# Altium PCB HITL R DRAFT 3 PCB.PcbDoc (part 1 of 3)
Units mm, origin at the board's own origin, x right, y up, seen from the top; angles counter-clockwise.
Board outline 90 x 65 mm, 6 copper layers (L1, L2, L3, L4, L5, L6), stack 1.752 mm thick; 198 components, 194 nets, 830 pads, 458 vias.
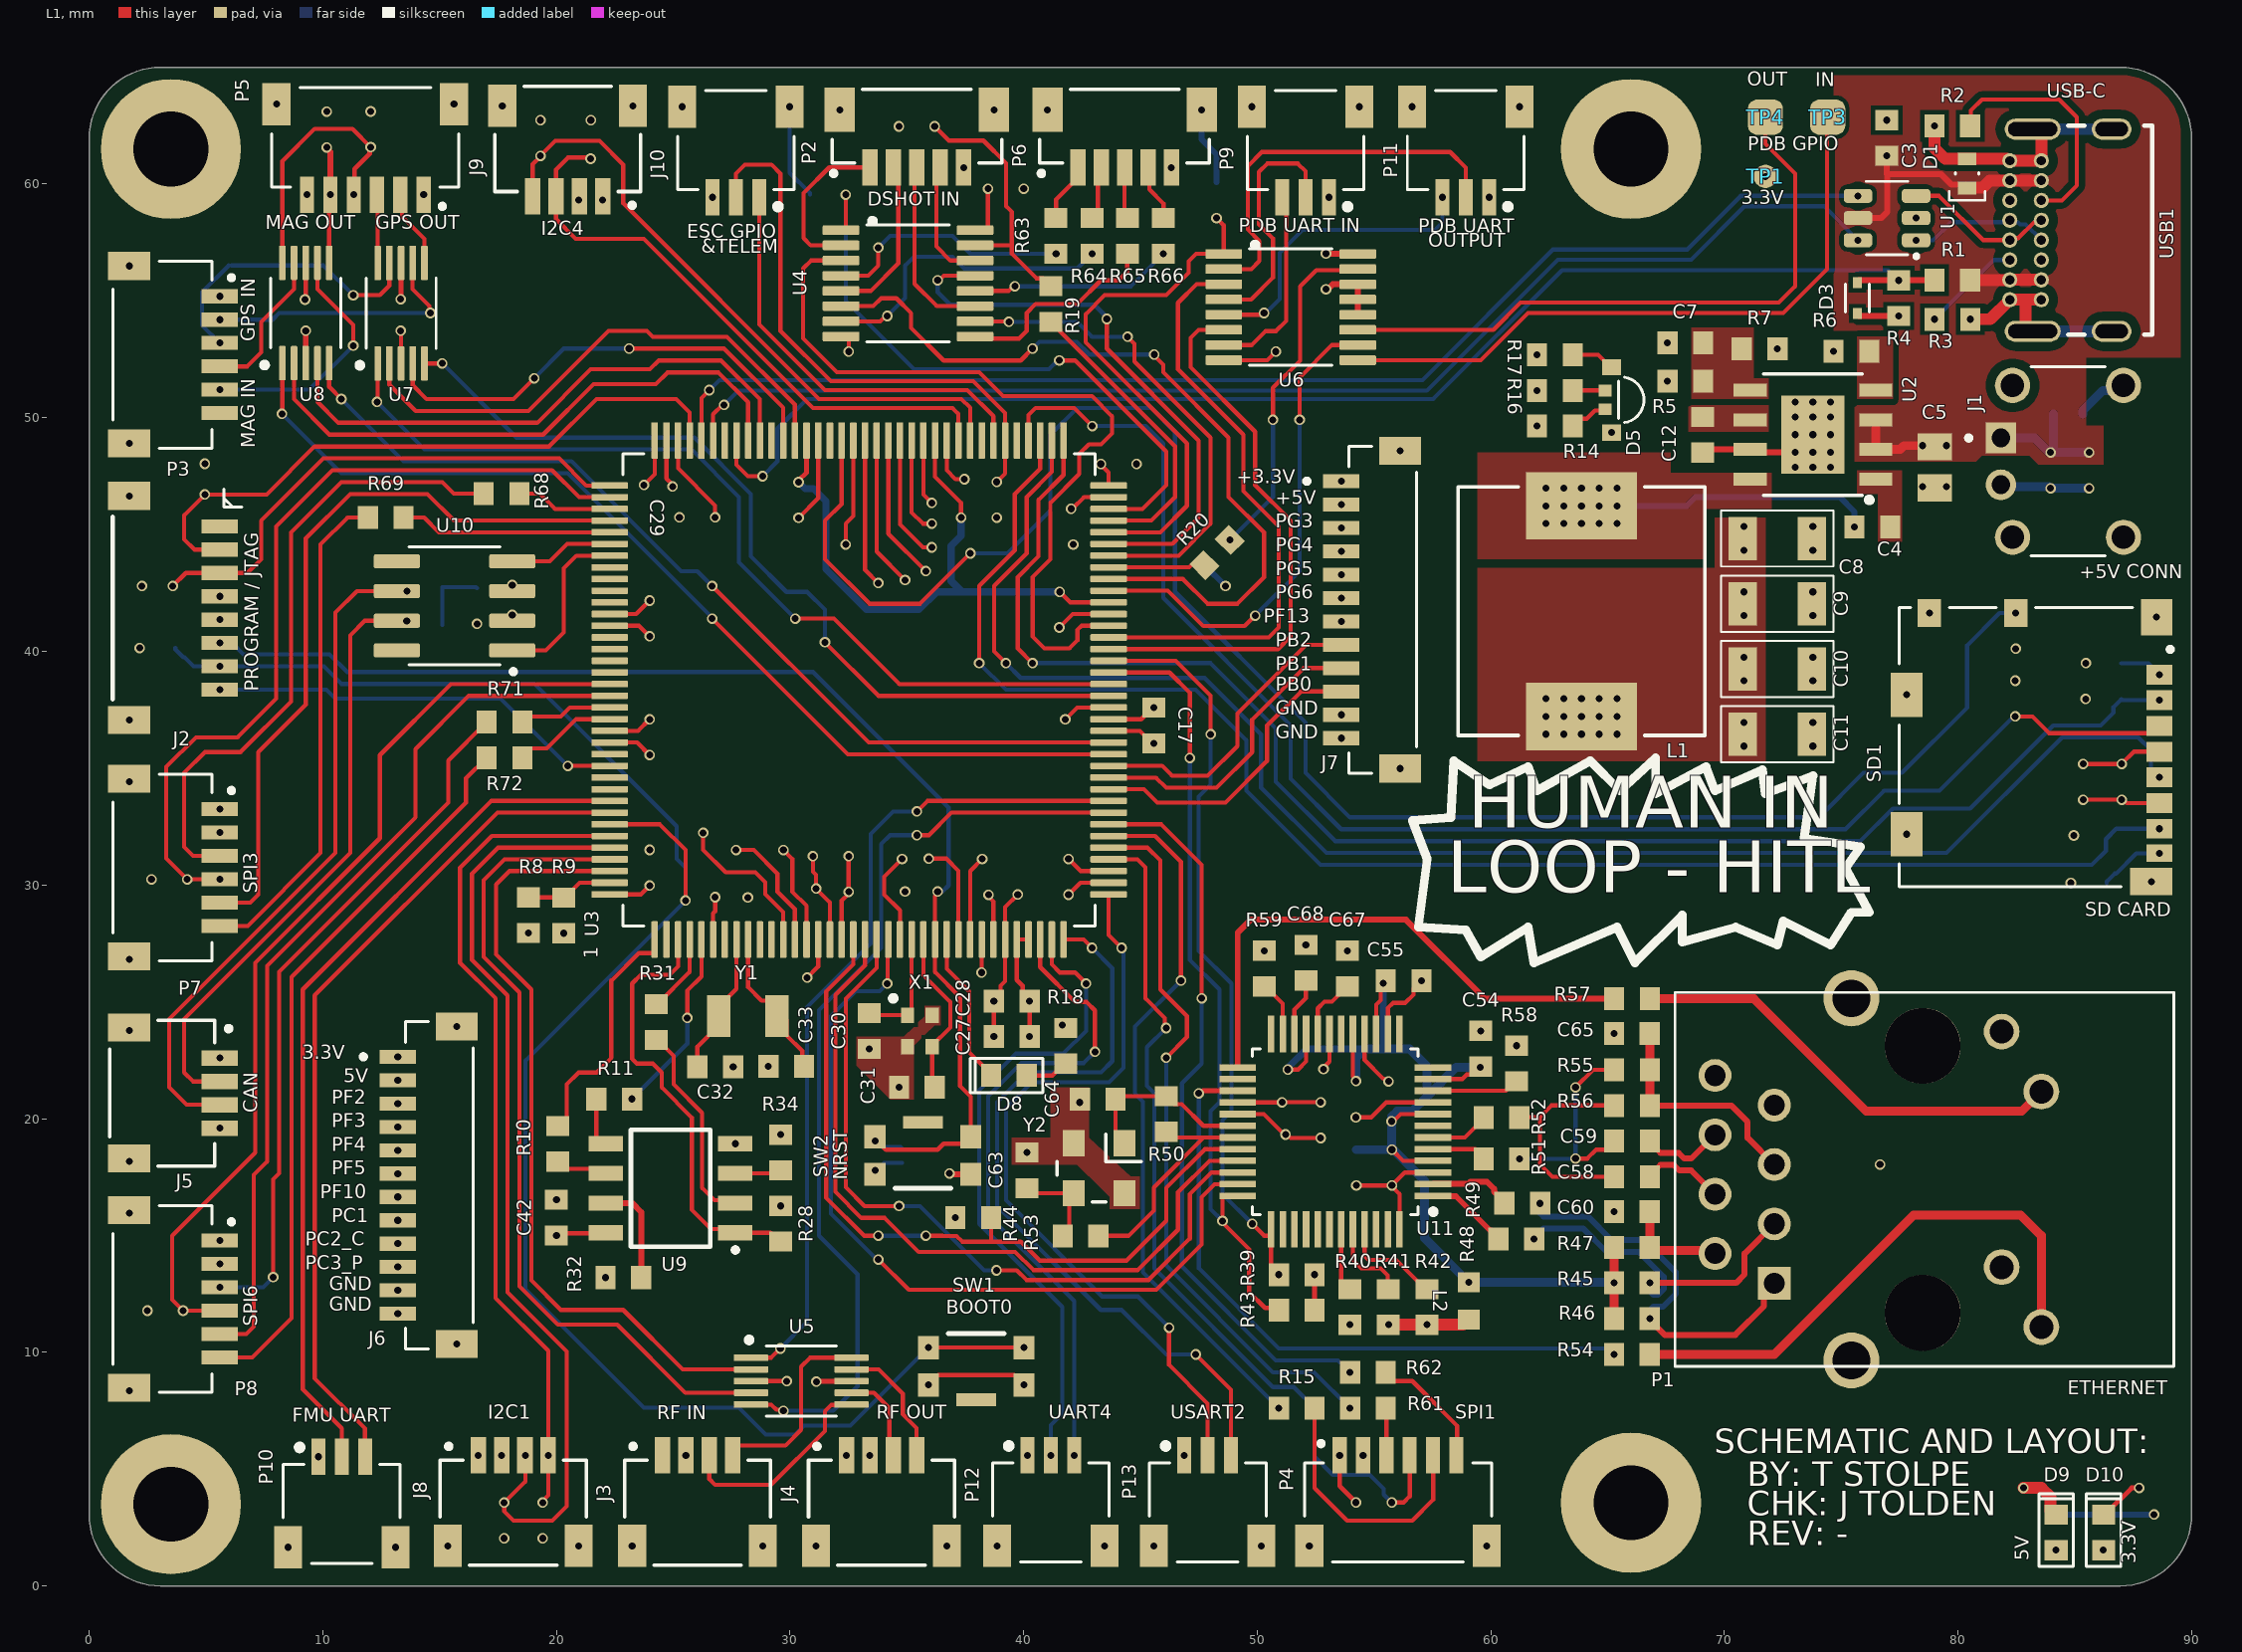
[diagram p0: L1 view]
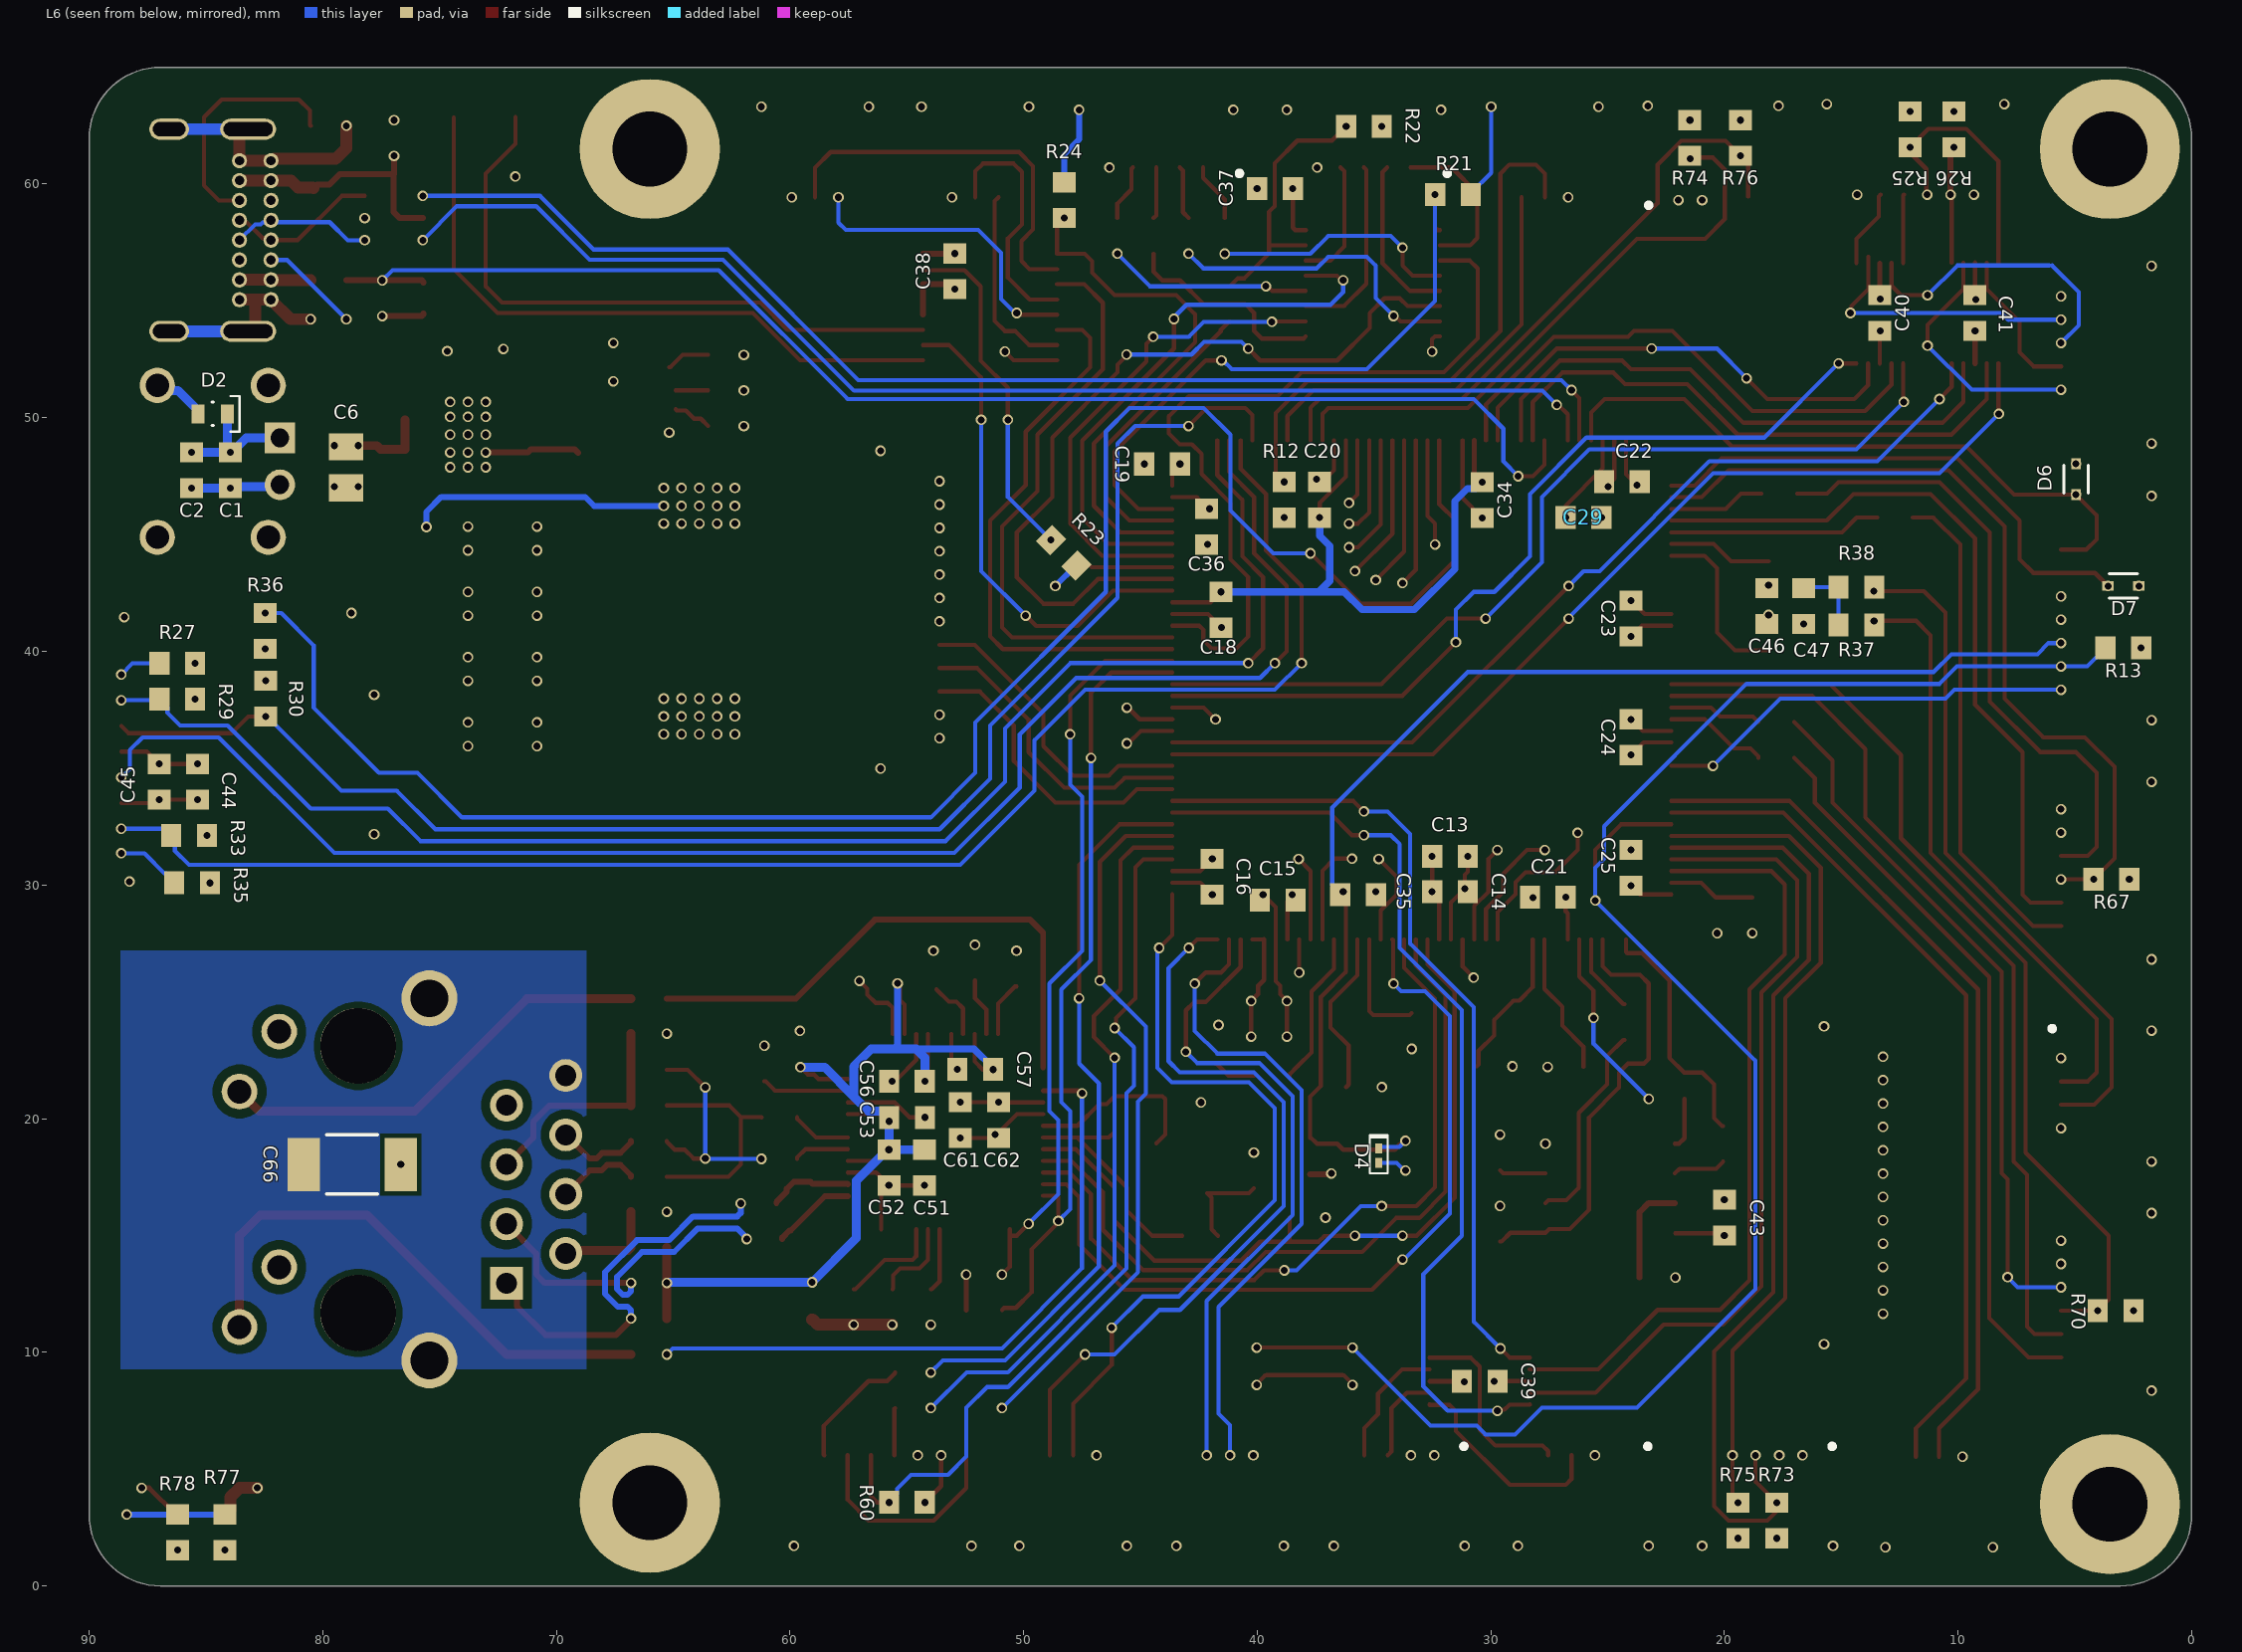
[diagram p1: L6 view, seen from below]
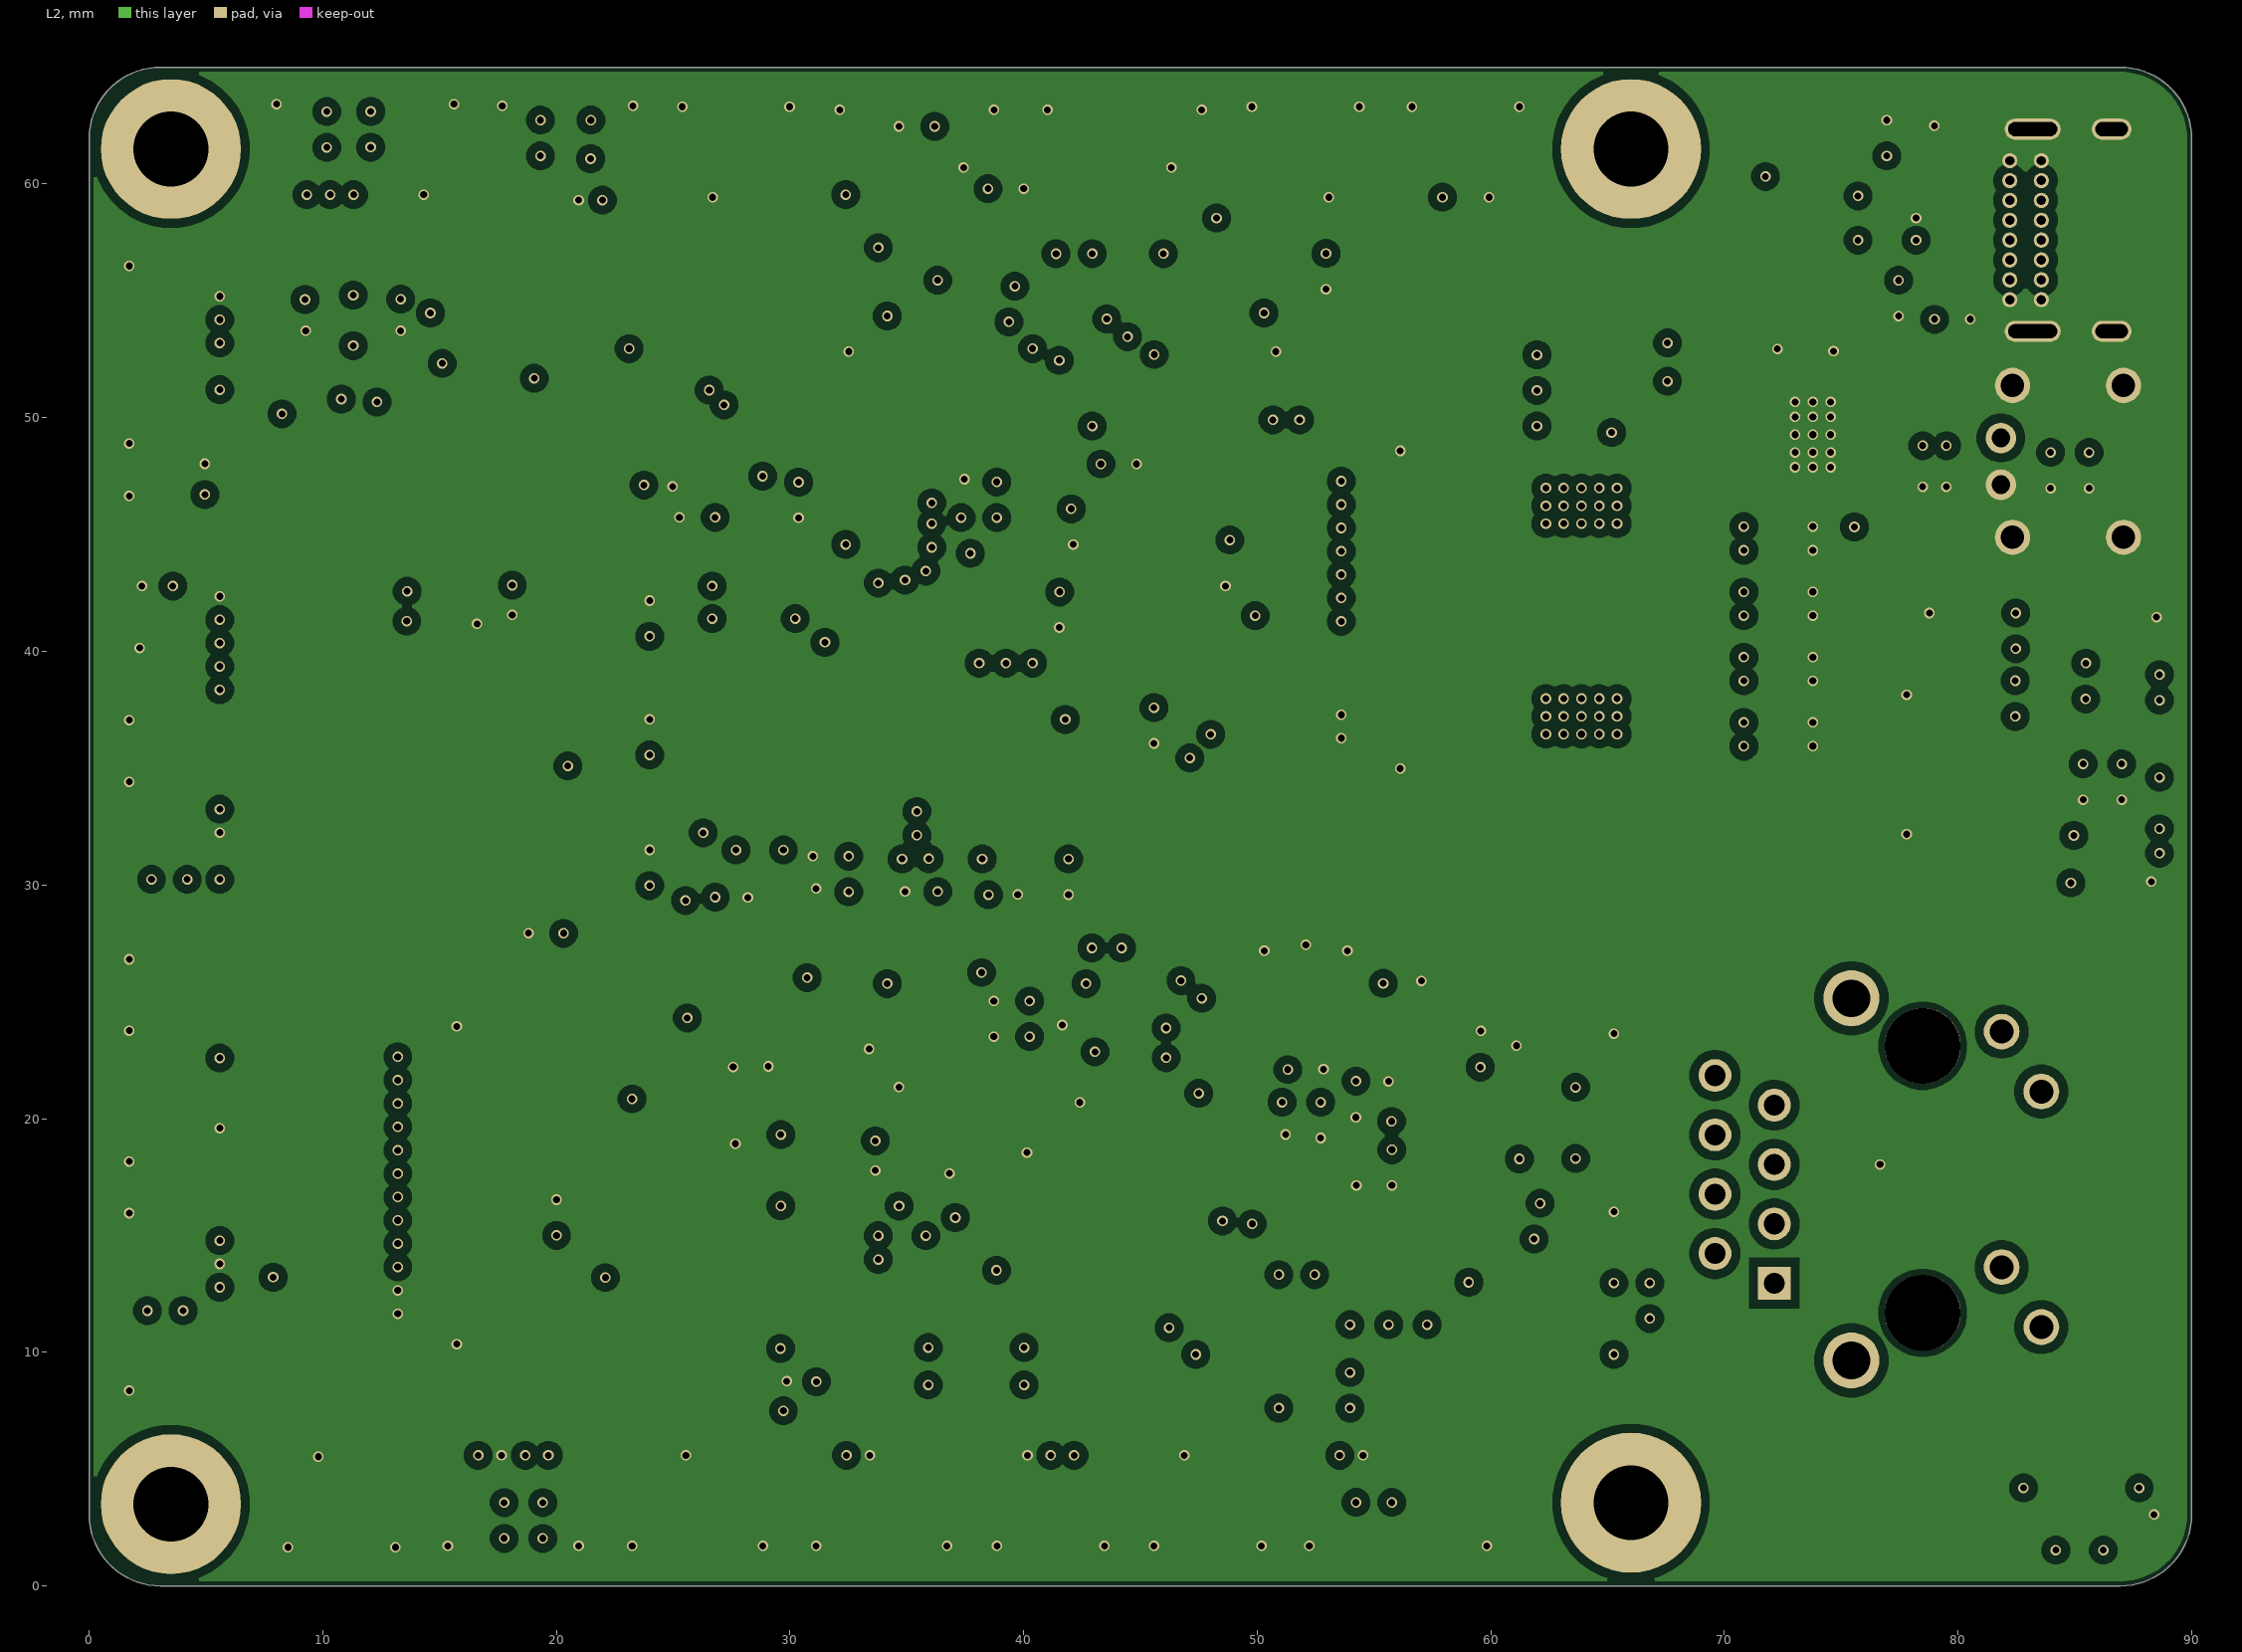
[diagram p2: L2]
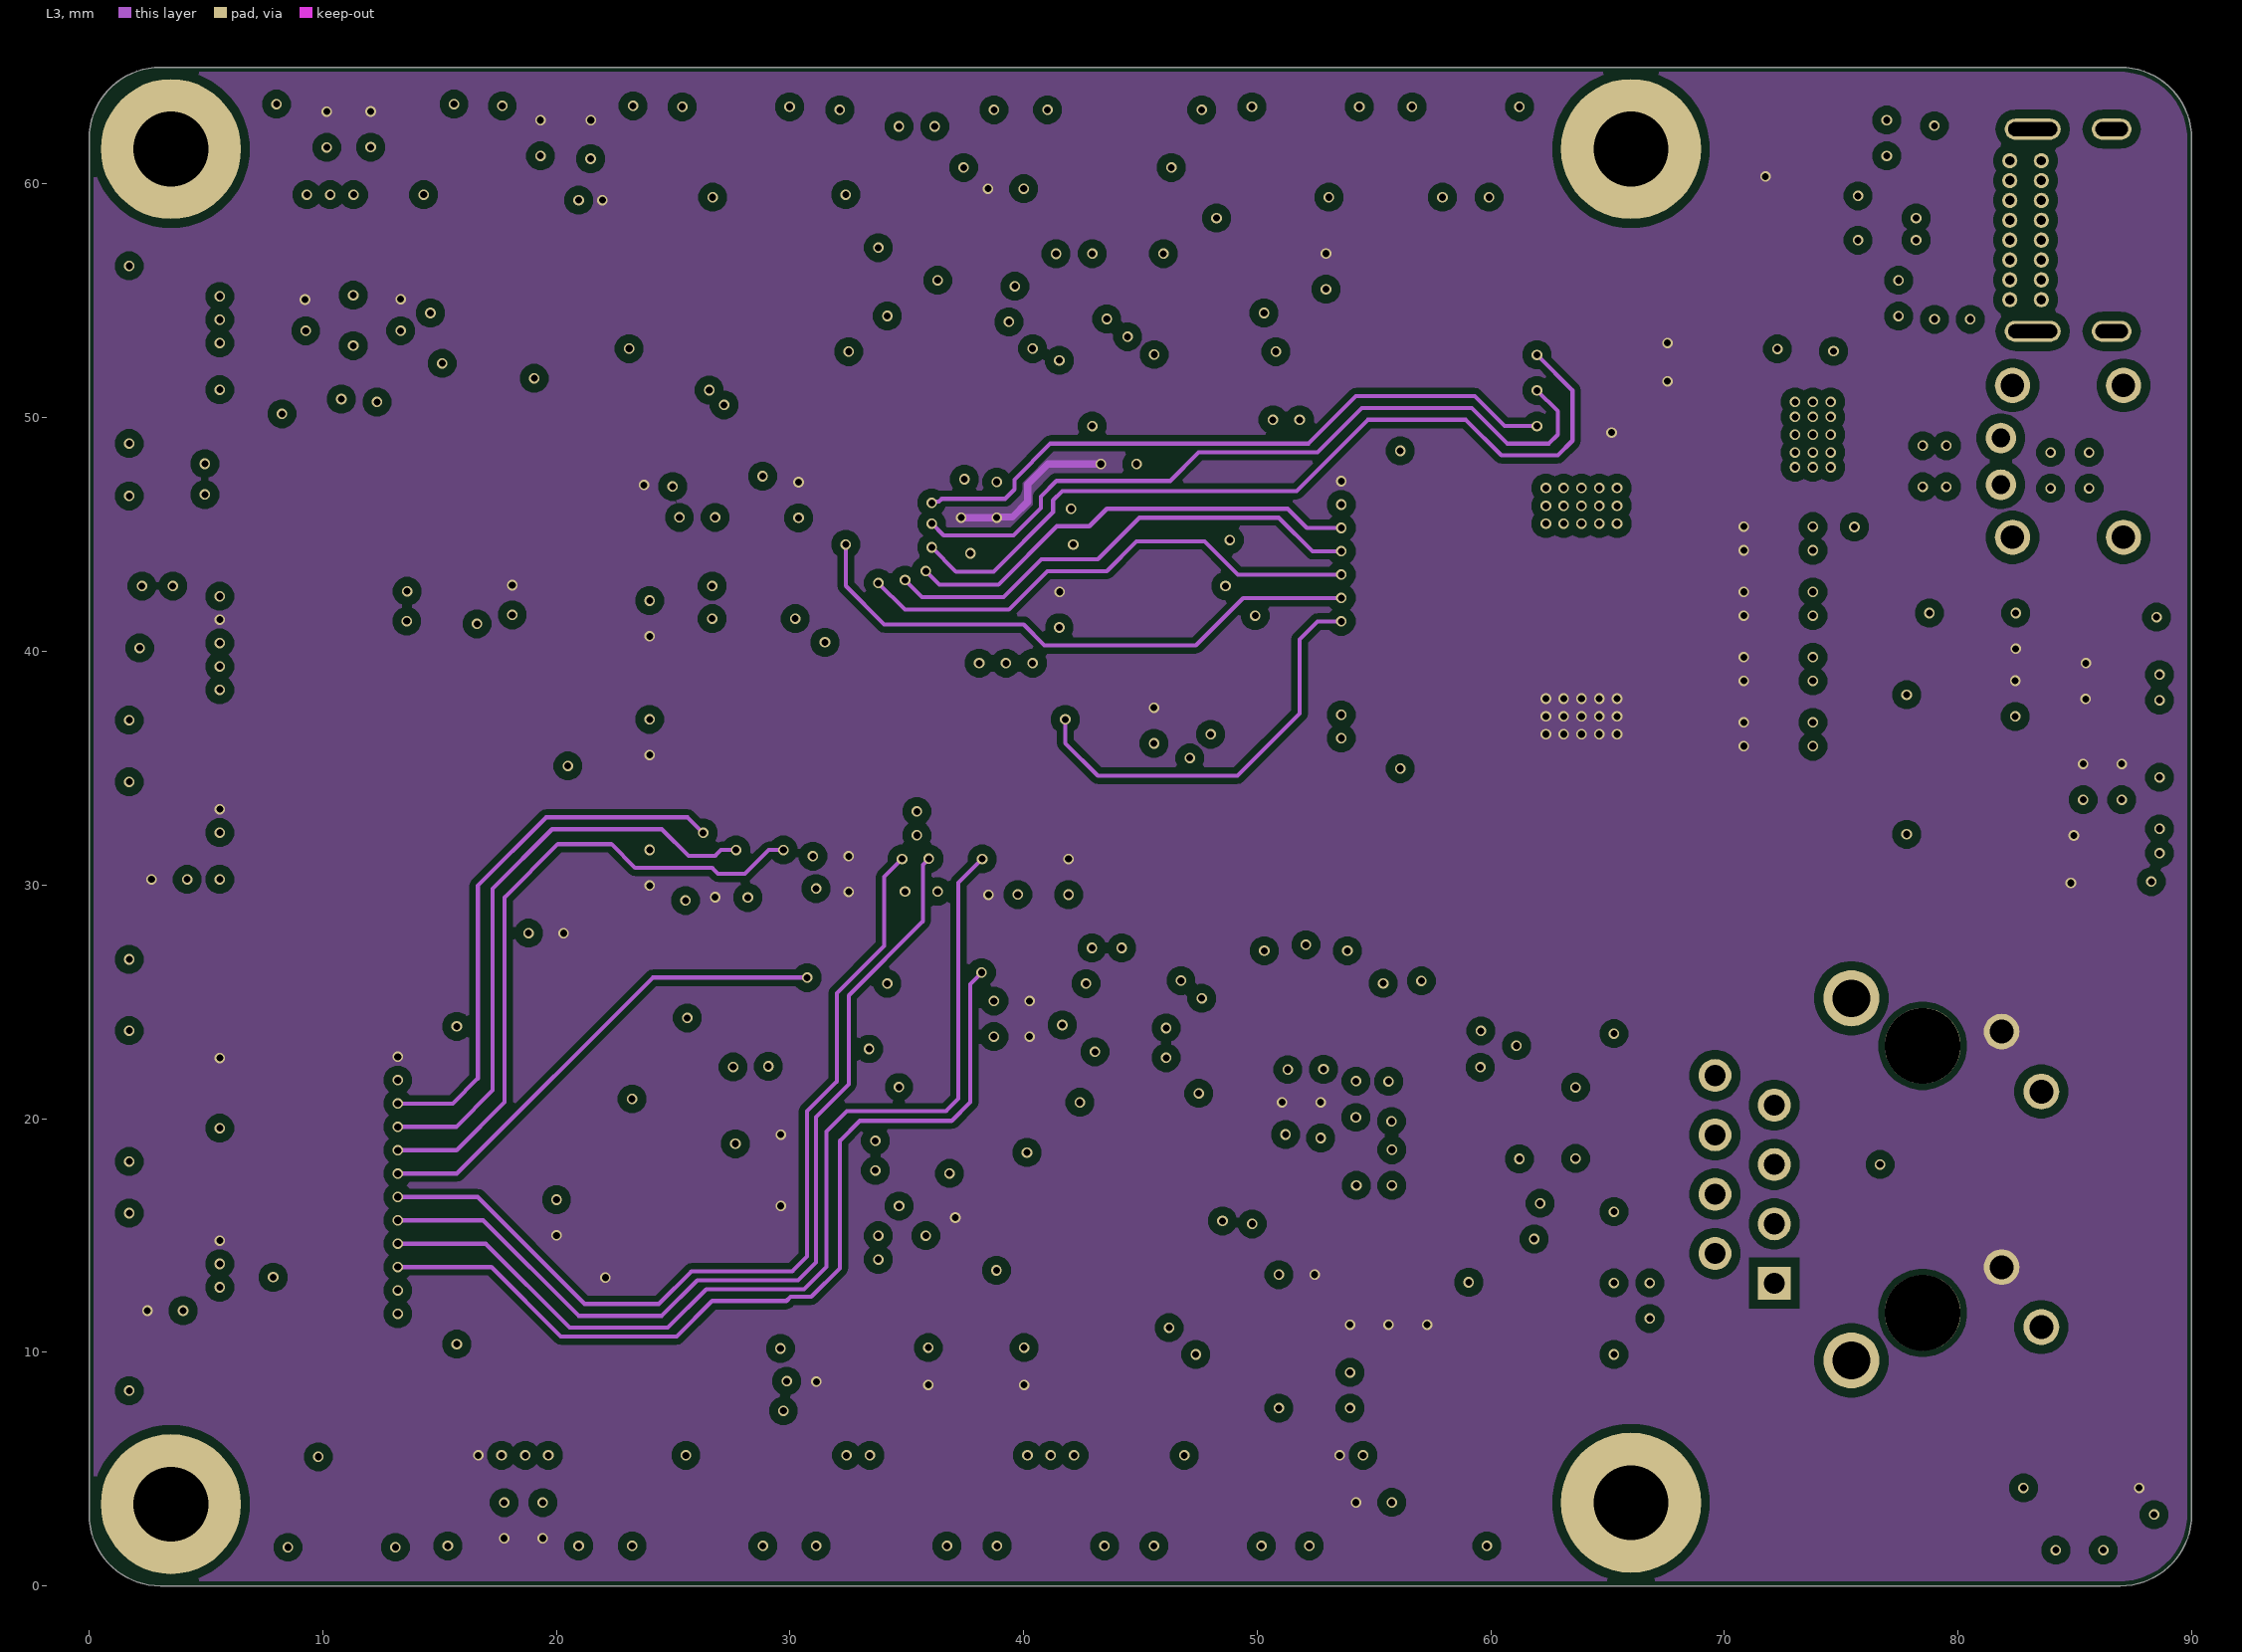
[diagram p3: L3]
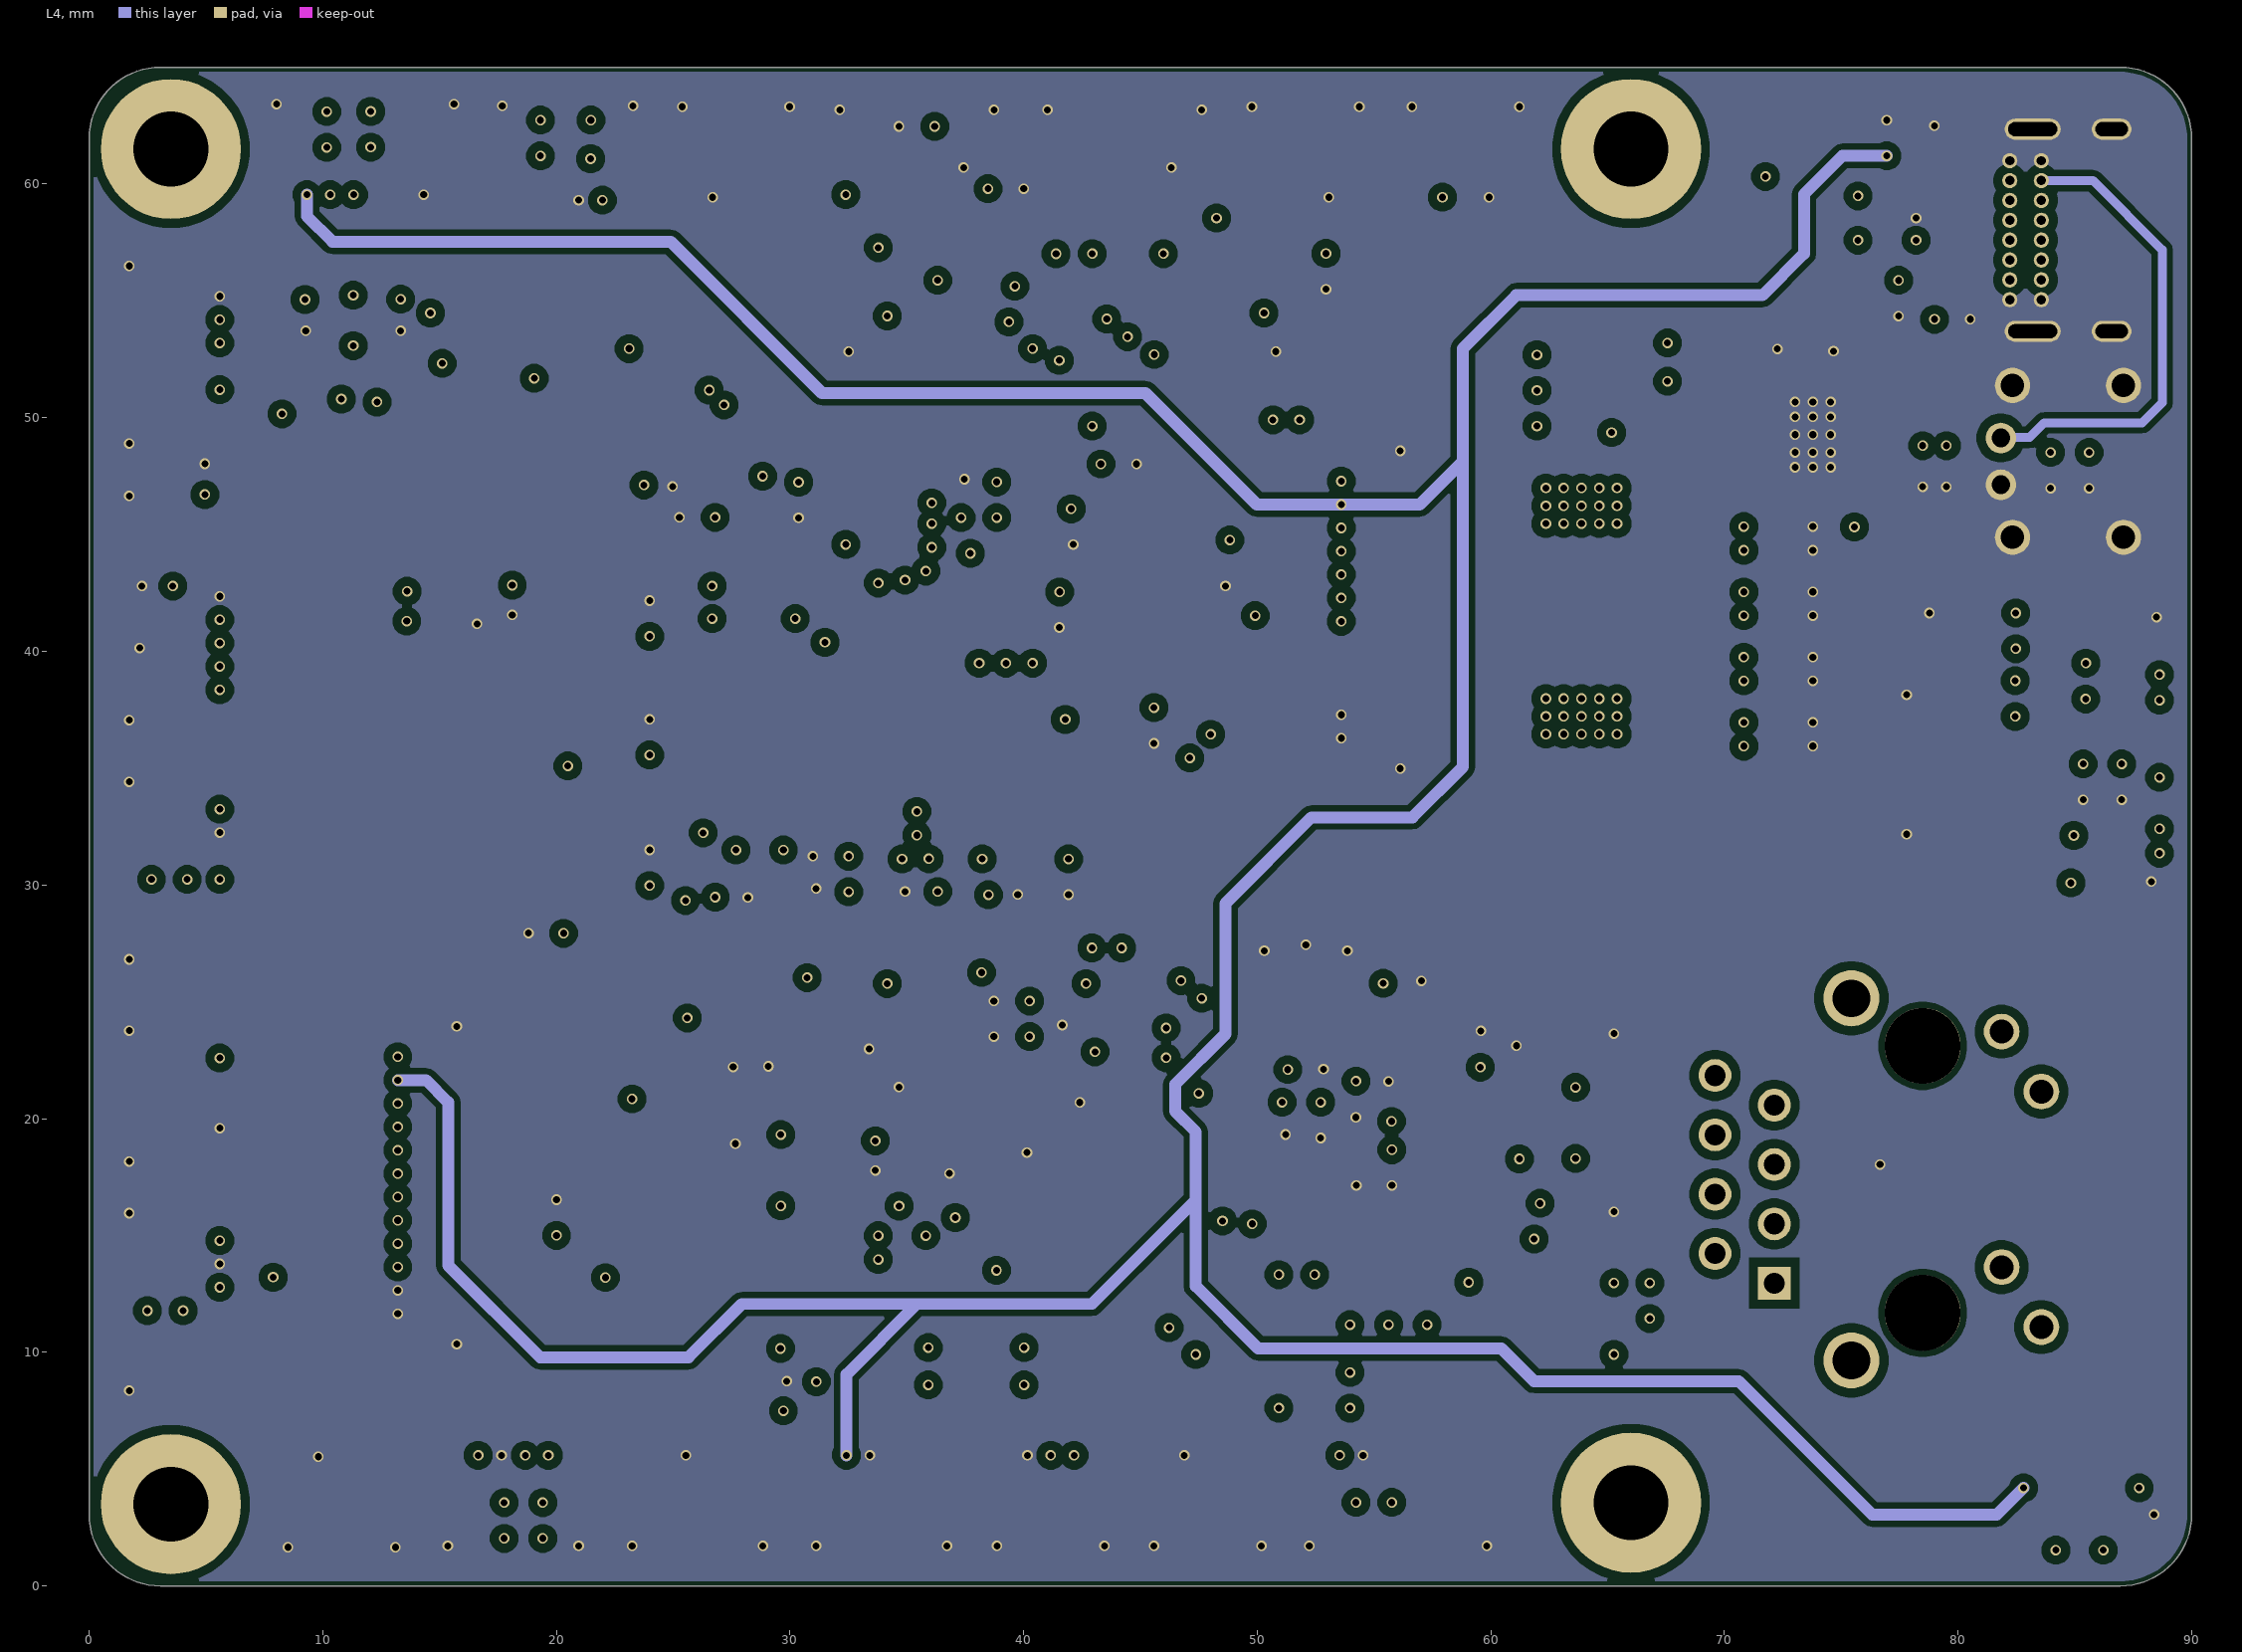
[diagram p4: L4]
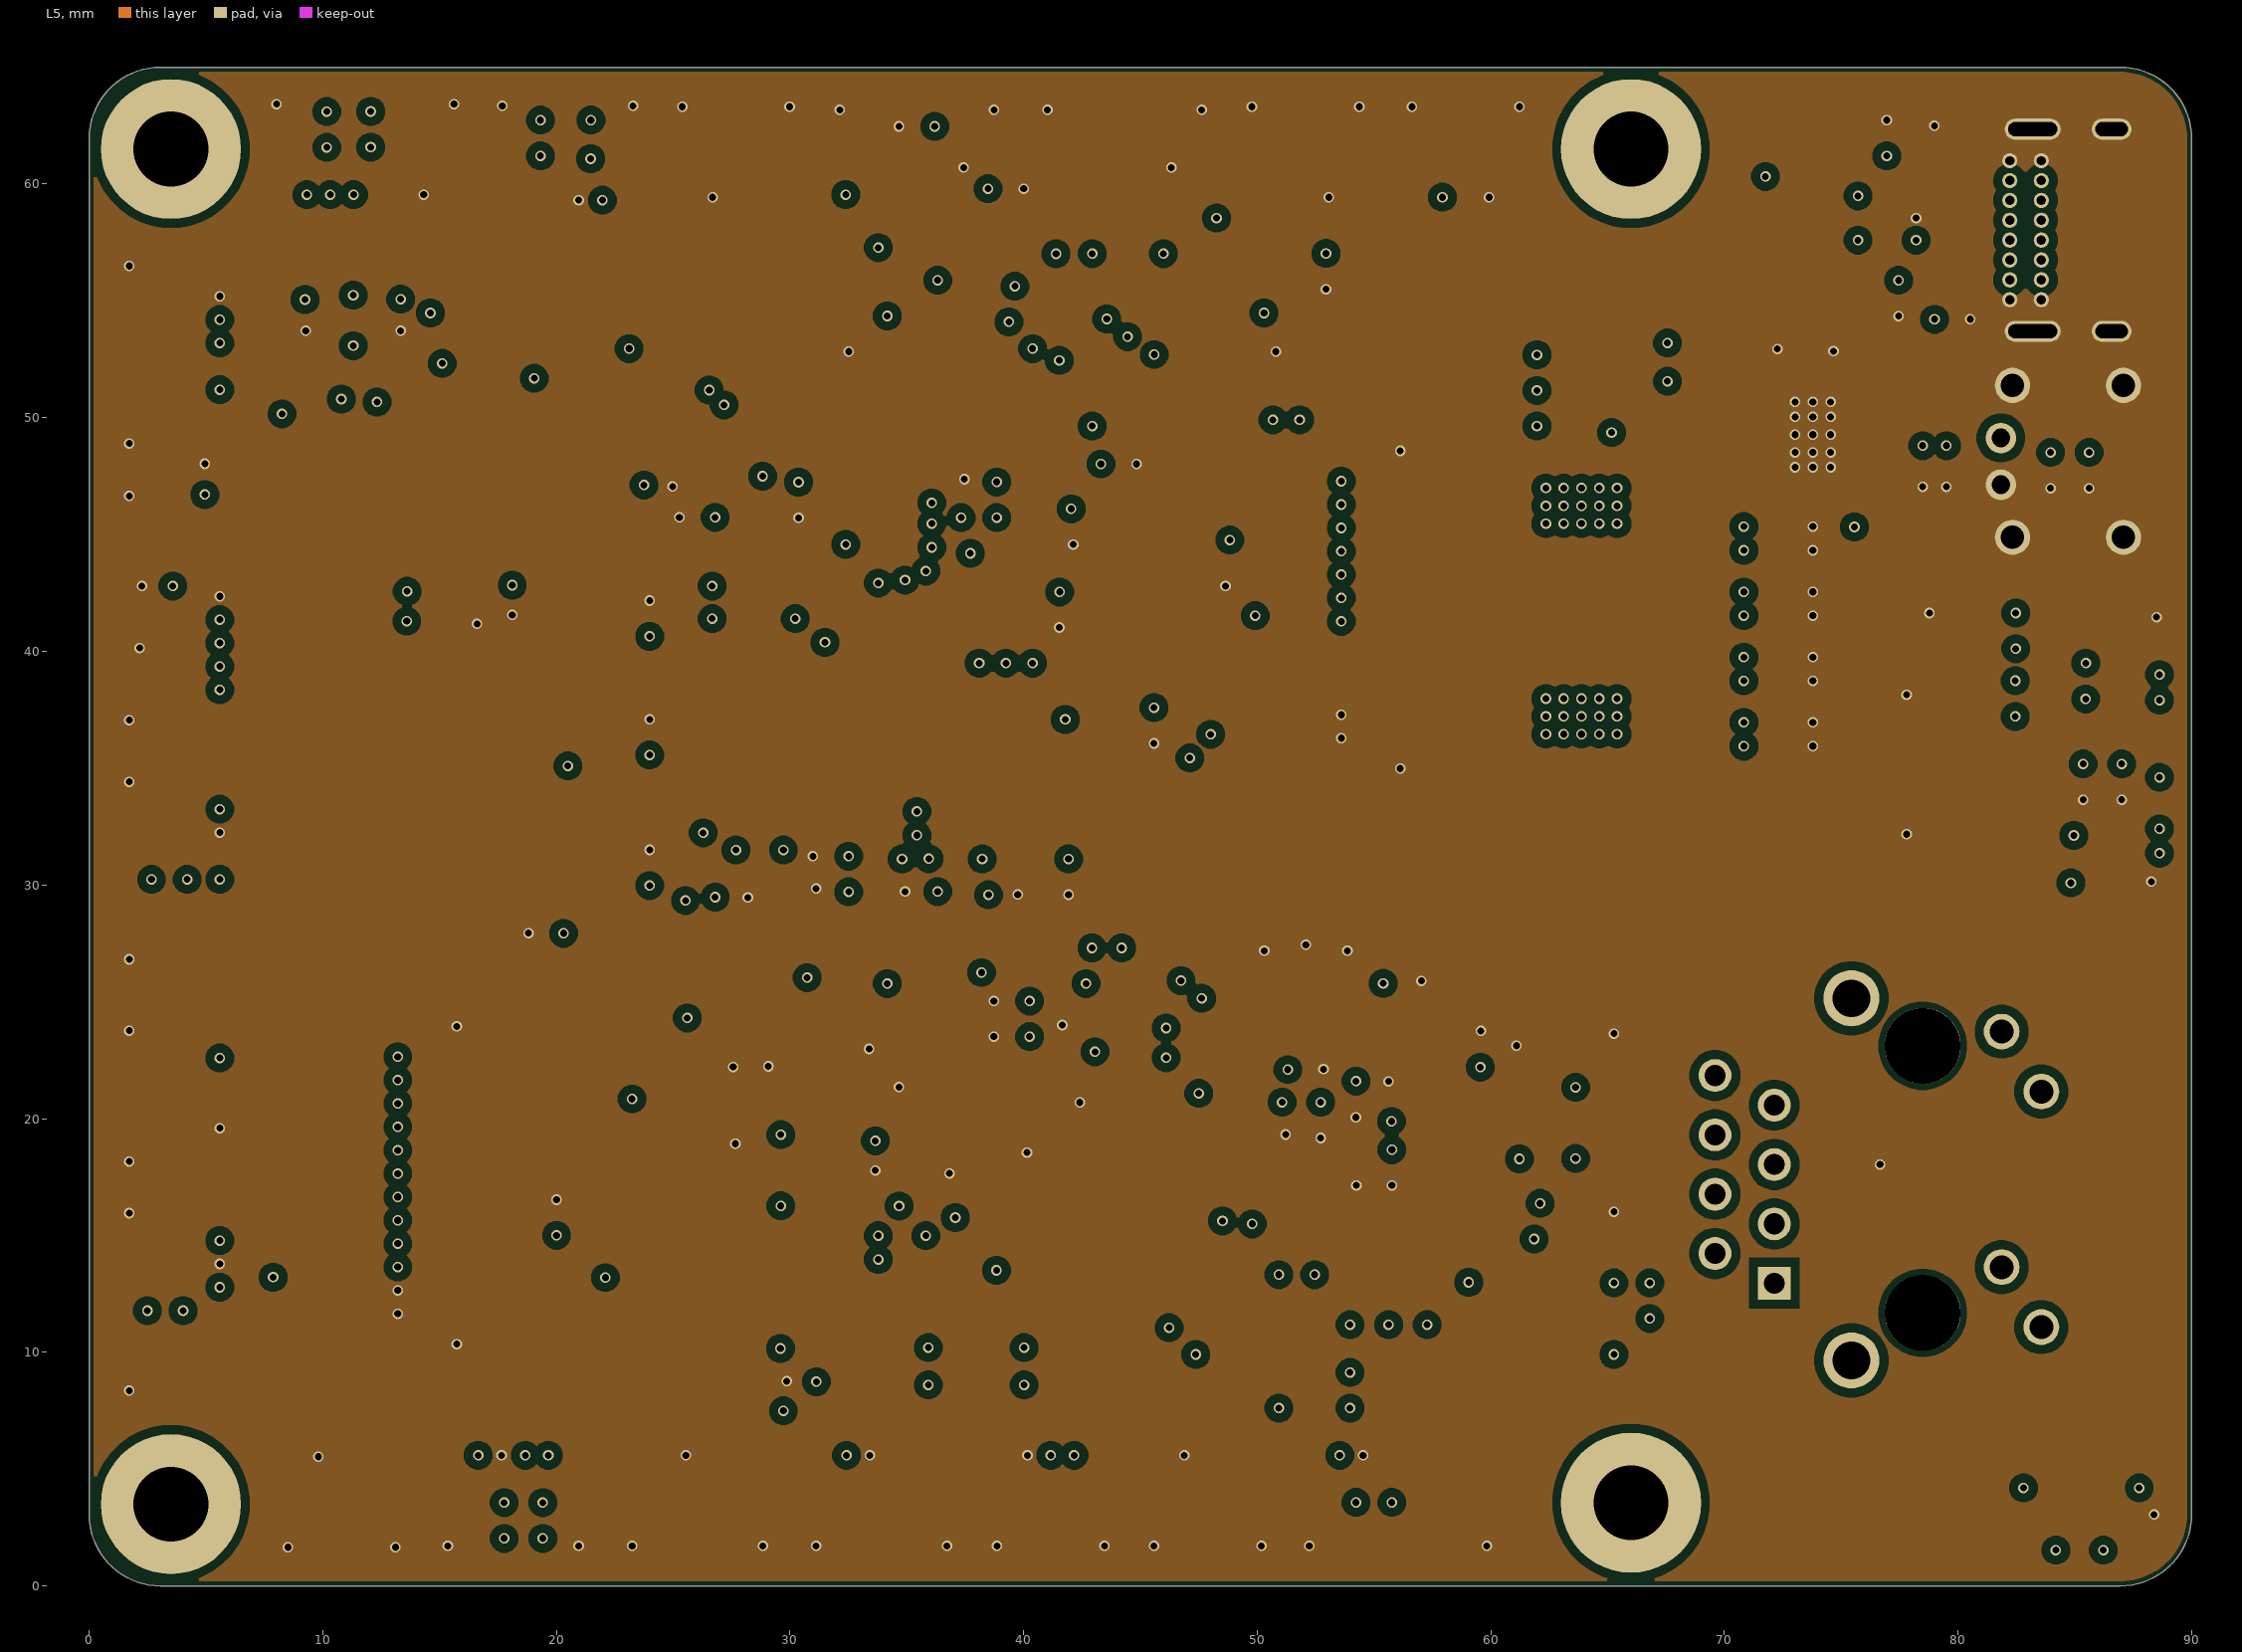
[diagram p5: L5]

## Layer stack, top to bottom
Top Solder: solder mask 0.0102, Solder Resist, Dk 3.5
L1: signal copper 0.035
Dielectric 1: prepreg 0.0711, PP-006, Dk 4.1
L2: signal copper 0.035
PREPREG1: prepreg 0.2, PP-006, Dk 4.1
L3: signal copper 0.035
CORE: core 1, Core-042, Dk 4.6
L4: signal copper 0.035
PREPREG2: prepreg 0.2, PP-006, Dk 4.1
L5: signal copper 0.035
Dielectric 2: prepreg 0.0711, PP-006, Dk 4.1
L6: signal copper 0.035
Bottom Solder: solder mask 0.0102, Solder Resist, Dk 3.5

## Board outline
0,3.048 0,61.952 cw(c3.048,61.952) 3.048,65 86.952,65 cw(c86.952,61.952) 90,61.952 90,3.048 cw(c86.952,3.048) 86.952,0 3.048,0 cw(c3.048,3.048)

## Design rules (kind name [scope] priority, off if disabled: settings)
BoardOutlineClearance [All] p1: gap=0.2 ignorepadtopadclearanceinfootprint=FALSE
Clearance [All] p1: gap=0.254 ignorepadtopadclearanceinfootprint=TRUE except(0.152: Arc-Arc Arc-Track Arc-THPad Track-Track Track-THPad SMDPad-SMDPad SMDPad-THPad SMDPad-Via SMDPad-Text THPad-THPad THPad-Via THPad-Text Via-Via Via-Text Fill-Text Poly-Text Region-Text Text-Text; 0.178: SMDPad-Fill SMDPad-Poly SMDPad-Region; 0.203: Arc-SMDPad Track-SMDPad; 0.381: THPad-Fill THPad-Poly THPad-Region Via-Fill Via-Poly Via-Region; 0.457: SMDPad-Hole THPad-Hole)
ComponentClearance [All] p1: gap=0.102 collisioncheckmode=3 verticalgap=0.102 showdistances=TRUE
DiffPairsRouting [All] p1: maxlimit=0.508 minlimit=0.254 mostfreqgap=0.254 toplayer_minwidth=0.178 toplayer_maxwidth=0.635 toplayer_prefwidth=0.178 midlayer1_minwidth=0.178 midlayer1_maxwidth=0.635 midlayer1_prefwidth=0.178 midlayer2_minwidth=0.178 midlayer2_maxwidth=0.635 midlayer2_prefwidth=0.178 midlayer3_minwidth=0.178 midlayer3_maxwidth=0.635 midlayer3_prefwidth=0.178 midlayer4_minwidth=0.178 midlayer4_maxwidth=0.635 midlayer4_prefwidth=0.178 bottomlayer_minwidth=0.178 bottomlayer_maxwidth=0.635 bottomlayer_prefwidth=0.178 maxuncoupledlength=12.7
Height [All] p1: minheight=0 maxheight=1816.048 prefheight=12.7
HoleSize [All] p1: absolutevalues=TRUE maxlimit=6.3 minlimit=0.3 maxpercent=80.000 minpercent=20.000
HoleToHoleClearance [All] p1: gap=0.203 allowstackedmicrovias=FALSE
MinimumAnnularRing [All] p1: minimumring=0
MinimumSolderMaskSliver [All] p1: minsoldermaskwidth=0
PlaneClearance [All] p1: clearance=0.102
PlaneConnect PlaneConnectPowerPads [InPadClass('PowerPads')] p1: planeconnectstyle=Direct reliefexpansion=0.508 reliefentries=4 reliefconductorwidth=0.254 reliefairgap=0.254
PlaneConnect [All] p2: planeconnectstyle=Direct reliefexpansion=0.3 reliefentries=4 reliefconductorwidth=0.102 reliefairgap=0.102
PolygonConnect PolygonConnectPowerPads [All vs (InPadClass('PowerPads'))] p1: connectstyle=Direct reliefconductorwidth=0.254 reliefentries=4 polygonreliefangle="90 Angle" airgapwidth=0.254
PolygonConnect [All] p2: connectstyle=Direct reliefconductorwidth=0.102 reliefentries=4 polygonreliefangle="90 Angle" airgapwidth=0.102
RoutingVias [All] p1: holewidth=0.3 width=0.45 viastyle="Through Hole" minholewidth=0.299 minwidth=0.449 maxholewidth=0.301 maxwidth=0.452
SilkToSilkClearance [All] p1: silktosilkclearance=0
SilkToSolderMaskClearance [IsPad] p1: minsilkscreentomaskgap=0 clearancetoexposedcopper=TRUE
SolderMaskExpansion [All] p1: expansion=0.075 istentingtop=FALSE
SupplyNets "Schematic Supply Nets_11" [InNet('CGND')] p1: voltage=0.000
SupplyNets "Schematic Supply Nets_8" [InNet('+3.3V')] p2: voltage=0.000
SupplyNets "Schematic Supply Nets_5" [InNet('+5V')] p3: voltage=0.000
SupplyNets "Schematic Supply Nets_2" [InNet('+3V3A')] p4: voltage=0.000
SupplyNets "Schematic Supply Nets_1" [InNet('GND')] p5: voltage=0.000
Width [All] p1: maxlimit=1816.048 minlimit=0.102 preferedwidth=0.178
20 further rules are at their usual default settings.

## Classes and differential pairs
differential pair class USB_LINES: D
component class "HITL (PWR) SH2": C1 C2 C3 C4 C5 C6 C7 C8 C9 C10 C11 C12 D1 D2 D3 D9 D10 J1 L1 R1 R2 R3 R4 R5 R6 R7 R77 R78 TP1 U1 U2 USB1
component class "HITL (MUX) SH4": C37 C38 C39 C40 C41 R19 R20 R21 R22 R23 R24 R25 R26 U4 U5 U6 U7 U8
component class "HITL (MEMORY) SH5": C42 C43 C44 C45 R27 R28 R29 R30 R31 R32 R33 R34 R35 R36 SD1 U9
component class "HITL (MCU) SH3": C13 C14 C15 C16 C17 C18 C19 C20 C21 C22 C23 C24 C25 C27 C28 C29 C30 C31 C32 C33 C34 C35 C36 D4 D5 D6 D7 D8 J2 R8 R9 R10 R11 R12 R13 R14 R15 R16 R17 R18 SW1 SW2 U3 X1 Y1
component class "HITL (INTRFACE 2) SH7": J3 J4 J5 J6 J7 J8 J9 J10 P2 P3 P4 P5 P6 P7 P8 P9 P10 P11 P12 P13 R60 R61 R62 R63 R64 R65 R66 R67 R68 R69 R70 R71 R72 R73 R74 R75 R76 TP3 TP4
component class "HITL (INTRFACE 1) SH6": C46 C47 C51 C52 C53 C54 C55 C56 C57 C58 C59 C60 C61 C62 C63 C64 C65 C66 C67 C68 L2 P1 R37 R38 R39 R40 R41 R42 R43 R44 R45 R46 R47 R48 R49 R50 R51 R52 R53 R54 R55 R56 R57 R58 R59 U10 U11 Y2
differential pair TX: +TX_P -TX_N
differential pair TX3: +TX3_P -TX3_N
differential pair RX: +RX_P -RX_N
differential pair RX3: +RX3_P -RX3_N
differential pair RX2: +RX2_P -RX2_N
differential pair DOUT: +DOUT_P -DOUT_N
differential pair D: +D_P -D_N

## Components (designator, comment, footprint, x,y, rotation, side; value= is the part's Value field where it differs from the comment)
C1 "100nF" 0603#1 83.947,47.752 r90 bottom
C2 "1uF" 0603#1 85.598,47.752 r90 bottom
C3 "100nF" 0603#1 76.962,61.976 r90 top
C4 "100nF" 0603#1 76.327,45.339 r180 top
C5 "10uF" 0805 78.994,47.879 r90 top
C6 "10uF" 0805 78.994,47.879 r90 bottom
C7 "DNI" 0603#1 68.326,53.213 r180 top
C8 "47uF" 1206 72.263,44.831 r180 top
C9 "47uF" 1206 72.263,42.037 r180 top
C10 "47uF" 1206 72.263,39.243 r180 top
C11 "47uF" 1206 72.263,36.449 r180 top
C12 "10nF" 0603#1 69.088,49.276 r90 top
C13 "4.7uF" 0603#1 31.75,31.242 r0 bottom
C14 "100nF" 0603#1 31.75,29.718 r0 bottom
C15 "100nF" 0603#1 39.116,29.337 r180 bottom
C16 "100nF" 0603#1 41.91,30.353 r90 bottom
C17 "100nF" 0603#1 45.593,36.83 r90 top
C18 "100nF" 0603#1 41.529,41.783 r90 bottom
C19 "100nF" 0603#1 44.069,48.006 r180 bottom
C20 "100nF" 0603#1 37.338,46.482 r270 bottom
C21 "100nF" 0603#1 27.559,29.464 r180 bottom
C22 "100nF" 0603#1 24.384,47.244 r180 bottom
C23 "100nF" 0603#1 24.003,41.402 r270 bottom
C24 "100nF" 0603#1 24.003,36.322 r270 bottom
C25 "100nF" 0603#1 24.003,30.734 r270 bottom
C27 "1uF" 0603#1 39.497,23.495 r0 top
C28 "100n" 0603#1 39.497,25.019 r0 top
C29 "2.2uF" 0603#2 26.035,45.72 r0 bottom
C30 "6pF" 0603#1 33.401,23.749 r90 top
C31 "6pF" 0603#1 35.433,21.336 r0 top
C32 "6pF" 0603#1 26.797,22.225 r180 top
C33 "6pF" 0603#1 29.845,22.225 r0 top
C34 "1uF" 0603#1 30.353,46.482 r90 bottom
C35 "100nF" 0603#1 35.687,29.591 r0 bottom
C36 "2.2uF" 0603#1 42.164,45.339 r90 bottom
C37 "100nF" 0603#1 39.243,59.817 r0 bottom
C38 "100nF" 0603#1 52.959,56.261 r270 bottom
C39 "100nF" 0603#1 30.48,8.763 r0 bottom
C40 "100nF" 0603#1 13.335,54.483 r90 bottom
C41 "100nF" 0603#1 9.271,54.483 r90 bottom
C42 "100nF" 0603#1 19.992,15.759 r270 top
C43 "4.7uF" 0603#1 20.018,15.759 r270 bottom
C44 "1uF" 0603#1 85.344,34.417 r90 bottom
C45 "0.1uF" 0603#1 86.995,34.417 r90 bottom
C46 "100nF" 0603#1 18.18,41.944 r90 bottom
C47 "4.7nF" 0603#1 16.587,41.944 r90 bottom
C51 "1uF" 0603#1 54.229,17.907 r90 bottom
C52 "100nF" 0603#1 55.753,17.907 r90 bottom
C53 "100nF" 0603#1 54.991,20.066 r0 bottom
C54 "100nF" 0603#1 59.563,22.987 r270 top
C55 "100nF" 0603#1 56.261,25.908 r180 top
C56 "100nF" 0603#1 54.991,21.59 r180 bottom
C57 "100nF" 0603#1 52.07,22.098 r180 bottom
C58 "6.8nF" 0603#1 66.04,17.526 r180 top
C59 "6.8nF" 0603#1 66.04,19.05 r180 top
C60 "22nF" 0603#1 66.04,16.002 r0 top
C61 "10uF" 0603#1 52.705,19.939 r90 bottom
C62 "100nF" 0603#1 51.054,19.939 r90 bottom
C63 "33pF" 0603#1 40.132,17.78 r270 top
C64 "33pF" 0603#1 43.18,20.828 r0 top
C65 "10nF" 0603#1 66.04,23.622 r0 top
C66 "1808GC102KAT2A" CAP_1808_AVX 78.74,18.034 r0 bottom
C67 "4.7uF" 0603#1 53.848,26.416 r270 top
C68 "10nF" 0603#1 52.07,26.67 r270 top
D1 "ESDA7P120-1U1M" TVS_ESDA7P120-1U1M 80.391,60.452 r90 top
D2 "ESDA7P120-1U1M" TVS_ESDA7P120-1U1M 84.709,50.165 r0 bottom
D3 "LESD5D5.0CT1G" TVS_LESD5D5.0CT1G 75.692,55.118 r270 top
D4 "ESDALC6V1-1U2" DIODE_ESDALC6V1-1U2 34.798,18.415 r270 bottom
D5 "MHS110FRGBCT" MHS110FRGBCT 65.47,50.762 r270 top
D6 "LESD5D5.0CT1G" TVS_LESD5D5.0CT1G 4.953,47.371 r270 bottom
D7 "LESD5D5.0CT1G" TVS_LESD5D5.0CT1G 2.921,42.799 r0 bottom
D8 "BLUE, 0603" 0603_LED 39.37,21.844 r180 top
D9 "GRN, 0603" 0603_LED 84.201,2.286 r90 top
D10 "GRN, 0603" 0603_LED 86.233,2.286 r90 top
J1 "M80-8420242" HARWIN_M80-8420242 84.709,48.133 r90 top (schematic designator J?)
J2 "SM08B-SRSS-TB" JST_SM08B-SRSS-TB 0.813,41.854 r270 top
J3 "SM04B-SRSS-TB(LF)(SN)" CONN_SM04B_JST 24.543,5.588 r0 top
J4 "SM04B-SRSS-TB(LF)(SN)" CONN_SM04B_JST 32.417,5.588 r0 top
J5 "SM04B-SRSS-TB(LF)(SN)" CONN_SM04B_JST 5.588,22.59 r270 top
J6 "BM12B-SRSS-TB(LF)(SN)" JST_BM12B-SRSS-TB(LF)(SN) 14.986,17.145 r270 top
J7 "BM12B-SRSS-TB(LF)(SN)" JST_BM12B-SRSS-TB(LF)(SN) 55.372,41.783 r270 top
J8 "SM04B-SRSS-TB(LF)(SN)" CONN_SM04B_JST 16.653,5.588 r0 top
J9 "SM04B-SRSS-TB(LF)(SN)" CONN_SM04B_JST 21.984,59.472 r180 top
J10 "SM03B-SRSS-TB(LF)(SN)" JST_SM03B-SRSS-TB(LF)(SN) 27.686,59.436 r180 top
L1 "SRP1050WA-5R6M" IND_SRP1050_BRN 63.881,41.722 r90 top
L2 "HCB 1608KF-601T20" IND_HCB1608KF_TTA 59.055,12.192 r270 top
P1 "J1B1211CCD" J1B1211CCD 78.486,17.399 r90 top
P2 "SM05B-SRSS-TB(LF)(SN)" CONN5_SM05B-SRSS_JST 35.433,62.484 r0 top
P3 "SM06B-SRSS-TB(LF)(SN)" JST_SM06B-SRSS-TB(LF)(SN) 5.588,52.697 r270 top
P4 "SM06B-SRSS-TB(LF)(SN)" JST_SM06B-SRSS-TB(LF)(SN) 56.031,5.588 r0 top
P5 "SM06B-SRSS-TB(LF)(SN)" JST_SM06B-SRSS-TB(LF)(SN) 11.818,59.548 r180 top
P6 "SM05B-SRSS-TB(LF)(SN)" CONN5_SM05B-SRSS_JST 44.323,62.484 r0 top
P7 "SM06B-SRSS-TB(LF)(SN)" JST_SM06B-SRSS-TB(LF)(SN) 5.588,30.742 r270 top
P8 "SM06B-SRSS-TB(LF)(SN)" JST_SM06B-SRSS-TB(LF)(SN) 5.588,12.279 r270 top
P9 "SM03B-SRSS-TB(LF)(SN)" JST_SM03B-SRSS-TB(LF)(SN) 52.07,59.436 r180 top
P10 "SM03B-SRSS-TB(LF)(SN)" JST_SM03B-SRSS-TB(LF)(SN) 10.809,5.526 r0 top
P11 "SM03B-SRSS-TB(LF)(SN)" JST_SM03B-SRSS-TB(LF)(SN) 58.927,59.436 r180 top
P12 "SM03B-SRSS-TB(LF)(SN)" JST_SM03B-SRSS-TB(LF)(SN) 41.164,5.588 r0 top
P13 "SM03B-SRSS-TB(LF)(SN)" JST_SM03B-SRSS-TB(LF)(SN) 47.879,5.588 r0 top
R1 "33K, 0.1%" 0603#1 79.756,55.88 r0 top
R2 "5.1K" 0603#1 79.756,62.484 r0 top
R3 "5.1K" 0603#1 79.756,54.229 r180 top
R4 "82K, 0.1%" 0603#1 77.47,55.118 r90 top
R5 "31.6K" 0603#1 68.325,51.575 r180 top
R6 "200K" 0603#1 75.438,52.832 r0 top
R7 "10K" 0603#1 71.501,52.959 r180 top
R8 "DNI" 0603#1 18.796,28.702 r270 top
R9 "0R" 0603#1 20.32,28.702 r90 top
R10 "22R" 0603#1 20.066,18.923 r90 top
R11 "22R" 0603#1 22.479,20.828 r0 top
R12 "DNI" 0603#1 38.862,46.482 r270 bottom
R13 "10K" 0603#1 2.921,40.132 r180 bottom
R14 "470R" 0603#1 62.738,49.657 r180 top
R15 "22R" 0603#1 51.689,7.62 r180 top
R16 "470R" 0603#1 62.738,51.181 r180 top
R17 "470R" 0603#1 62.738,52.705 r180 top
R18 "3.3K" 0603#1 41.783,23.114 r270 top
R19 "0R" 0603#1 41.148,54.864 r270 top
R20 "0R" 0603#1 48.275,44.233 r225 top
R21 "10K" 0603#1 31.623,59.563 r0 bottom
R22 "10K" 0603#1 35.433,62.484 r0 bottom
R23 "10K" 0603#1 48.275,44.233 r45 bottom
R24 "10K" 0603#1 48.273,59.308 r270 bottom
R25 "DNI" 0603#1 12.064,62.342 r270 bottom
R26 "DNI" 0603#1 10.159,62.342 r90 bottom
R27 "47K" 0603#1 86.233,39.497 r0 bottom
R28 "10K" 0603#1 29.591,15.494 r270 top
R29 "47K" 0603#1 86.233,37.973 r0 bottom
R30 "47K" 0603#1 82.461,37.973 r270 bottom
R31 "22R" 0603#1 24.257,24.13 r270 top
R32 "1K" 0603#1 22.86,13.208 r180 top
R33 "47K" 0603#1 85.725,32.131 r0 bottom
R34 "1K" 0603#1 29.591,18.542 r270 top
R35 "47K" 0603#1 85.598,30.099 r0 bottom
R36 "47K" 0603#1 82.461,40.88 r90 bottom
R37 "60R, 0.125W" 0603#1 14.351,41.148 r0 bottom
R38 "60R, 0.125W" 0603#1 14.343,42.74 r180 bottom
R39 "4.7K" 0603#1 51.689,13.335 r180 top
R40 "10K" 0603#1 53.975,11.938 r90 top
R41 "10K" 0603#1 55.626,11.938 r90 top
R42 "10K" 0603#1 57.277,11.938 r90 top
R43 "4.7K" 0603#1 51.689,11.811 r180 top
R44 "4.7K" 0603#1 37.846,15.748 r0 top
R45 "49.9R" 0603#1 66.04,12.954 r0 top
R46 "49.9R" 0603#1 66.04,11.43 r0 top
R47 "10R" 0603#1 66.04,14.478 r0 top
R48 "3.3R" 0603#1 61.087,14.859 r180 top
R49 "3.3R" 0603#1 61.341,16.383 r180 top
R50 "1MEG" 0603#1 46.101,20.193 r270 top
R51 "3.3R" 0603#1 60.452,18.288 r180 top
R52 "3.3R" 0603#1 60.452,20.066 r180 top
R53 "0R" 0603#1 42.443,14.967 r0 top
R54 "330R" 0603#1 66.033,9.919 r180 top
R55 "49.9R" 0603#1 66.04,22.098 r180 top
R56 "49.9R" 0603#1 66.04,20.574 r180 top
R57 "330R" 0603#1 66.04,25.146 r180 top
R58 "12.4K" 0603#1 61.087,22.352 r270 top
R59 "0R" 0603#1 50.292,26.416 r270 top
R60 "10K" 0603#1 54.991,3.556 r180 bottom
R61 "22R" 0603#1 54.737,7.62 r180 top
R62 "22R" 0603#1 54.737,9.144 r180 top
R63 "220R" 0603#1 41.402,57.785 r90 top
R64 "220R" 0603#1 42.926,57.785 r270 top
R65 "220R" 0603#1 44.45,57.785 r90 top
R66 "220R" 0603#1 45.974,57.785 r270 top
R67 "10K" 0603#1 3.429,30.226 r180 bottom
R68 "22R" 0603#1 17.653,46.736 r0 top
R69 "22R" 0603#1 12.7,45.72 r0 top
R70 "10K" 0603#1 3.252,11.764 r180 bottom
R71 "22R" 0603#1 17.78,36.957 r0 top
R72 "22R" 0603#1 17.78,35.433 r0 top
R73 "4.7K" 0603#1 17.78,2.794 r270 bottom
R74 "4.7K" 0603#1 21.463,61.976 r90 bottom
R75 "4.7K" 0603#1 19.431,2.794 r270 bottom
R76 "4.7K" 0603#1 19.304,61.976 r90 bottom
R77 "3.3K" 0603#1 84.201,2.286 r270 bottom
R78 "3.3K" 0603#1 86.233,2.286 r270 bottom
SD1 "104031-0811" MOLEX_104031-0811 83.174,35.901 r90 top
SW1 "KMR221GLFS" SW_KMR221GLFS 37.973,9.398 r180 top
SW2 "KMR221GLFS" SW_KMR221GLFS 35.687,18.415 r0 top
TP1 "TESTPAD" TESTPAD 71.755,60.325 r180 top
TP3 "FMU_PAD" FMU_PAD 74.422,62.865 r270 top
TP4 "FMU_PAD" FMU_PAD 71.755,62.865 r270 top
U1 "USBLC6-2SC6" SOT95P280X145-6N 76.962,58.547 r180 top
U2 "AP64502QSP-13" SO-8EP_DIO 73.787,49.276 r180 top
U3 "STM32H743ZIT6" QFP50P2200X2200X160-144N 32.959,38.346 r90 top locked
U4 "TMUX1574PWR" SOP65P640X120-16N 35.052,55.753 r0 top
U5 "TMUX1072DGSR" SOP50P490X110-10N 30.48,8.763 r0 top
U6 "TMUX1574PWR" SOP65P640X120-16N 51.435,54.737 r0 top
U7 "TMUX1072DGSR" SOP50P490X110-10N 13.351,54.474 r90 top
U8 "TMUX1072DGSR" SOP50P490X110-10N 9.271,54.483 r90 top
U9 "FM25V05-GTR" SOIC127P602X173-8N-1-V 24.892,17.018 r180 top
U10 "TCAN332GDR" SOIC127P599X175-8N 15.64,41.944 r180 top
U11 "W5500" QFP50P900X900X160-48N 53.344,19.442 r180 top
USB1 "USB4085-GF-A_REVA4" GCT_USB4085-GF-A_REVA4 86.576,58.027 r90 top
X1 "CS11321-25M" CS11321-25M_NDK 35.56,23.749 r0 top
Y1 "MU00525-32.768K" XTAL_NX3215SA-32.768KHZ-EXS00A-MU00525 28.194,24.384 r0 top
Y2 "X1E0000210352" "CRYSTAL4_X1E0000210132 TSX-3225 25 MHZ 9.0PF_EPS" 43.231,17.876 r270 top

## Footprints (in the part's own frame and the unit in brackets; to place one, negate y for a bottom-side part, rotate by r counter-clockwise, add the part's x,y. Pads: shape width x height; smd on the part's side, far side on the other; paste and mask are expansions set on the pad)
0603#1 [mm]
  rect 0.86x0.98 smd mask+0.05: 1(-0.769,0.013) 2(0.761,0.013)
  body extent -0.78,-0.41 0.77,0.44, height 0.55
0603#2 [mm]
  rect 0.86x0.98 smd mask+0.05: 1(-0.769,-0.013) 2(0.761,-0.013)
  body extent -0.78,-0.44 0.77,0.41, height 0.55
0603_LED [mm]
  rect 0.86x0.98 smd mask+0.05: 1(-0.765,0) 2(0.765,0)
  silkscreen extent -1.45,-0.74 1.65,0.74, body extent -0.77,-0.43 0.77,0.43, height 0.55
0805 [mm]
  rect 1.16x1.47 smd: 1(-0.88,0) 2(0.88,0)
  body extent -1,-0.63 1,0.63, height 0.94
1206 [mm]
  rect 1.21x1.86 smd paste+0 mask+0.102: 1(-1.477,0) 2(1.477,0)
  silkscreen extent -2.4,-1.2 2.4,1.2, body extent -1.6,-0.8 1.6,0.8, height 1.7
CAP_1808_AVX [mm]
  rect 1.376x2.28 smd paste+0 mask+0: 1(-2.078,0) 2(2.078,0)
  silkscreen extent -1.08,-1.27 1.08,1.27, body extent -2.41,-1.14 2.41,1.14, height 1.7
CONN5_SM05B-SRSS_JST [mil]
  rect 26x61 smd paste+0 mask+0: 1(-78.74,-69.77) 2(-39.37,-69.77) 3(0,-69.77) 4(39.37,-69.77) 5(78.74,-69.77)
  rect 51x75 smd paste+0 mask+0: 6(-129.92,27.47) 7(129.92,27.47)
  silkscreen extent -143,-83 143,62
CONN_SM04B_JST [mil]
  rect 26x61 smd paste+0 mask+0: 1(0,0) 2(39.37,0) 3(78.74,0) 4(118.11,0)
  rect 47x71 smd paste+0 mask+0: S1(-51.18,-152.56) S2(169.29,-152.56)
  silkscreen extent -64,-185 182,18
"CRYSTAL4_X1E0000210132 TSX-3225 25 MHZ 9.0PF_EPS" [mil]
  rect 44x37 smd paste+0 mask+0: 1(-42,42.82) 2(-42,-42.81) 3(42,-42.81) 4(42,42.82)
  silkscreen extent -57,-71 57,71, body extent -52,-66 52,66, height 24
CS11321-25M_NDK [mm]
  rect 0.559x0.66 smd paste+0 mask+0: 1(-0.525,0.675) 2(-0.525,-0.675) 3(0.525,-0.675) 4(0.525,0.675)
  silkscreen extent -1.24,1.3 -1.04,1.5, body extent -0.85,-1.05 0.85,1.05, height 0.38
DIODE_ESDALC6V1-1U2 [mm]
  rect 0.425x0.3 smd paste-1 mask+0.05: 1(-0.312,0) 2(0.312,0)
  silkscreen extent -0.89,-0.38 0.76,0.38, body extent -0.3,-0.15 0.3,0.15, height 0.33
FMU_PAD [mm]
  rrect50% 1.5x1.5 smd: 1(0,0)
GCT_USB4085-GF-A_REVA4 [mm]
  round 0.65 hole 0.4: A1(-2.975,4.36) A4(-2.125,4.36) A5(-1.275,4.36) A6(-0.425,4.36) A7(0.425,4.36) A8(1.275,4.36) A9(2.125,4.36) A12(2.975,4.36) B1(2.975,3.01) B4(2.125,3.01) B5(1.275,3.01) B6(0.425,3.01) B7(-0.425,3.01) B8(-1.275,3.01) B9(-2.125,3.01) B12(-2.975,3.01)
  oval 0.9x1.7 hole 0.6 slot 1.4 at 90 deg: S1(-4.325,0) S2(4.325,0)
  oval 0.9x2.4 hole 0.6 slot 2.1 at 90 deg: S3(-4.325,3.38) S4(4.325,3.38)
  silkscreen extent -4.47,-1.74 4.47,1.85, body extent -4.47,-4.25 4.47,4.92, height 3.46
HARWIN_M80-8420242 [mm]
  rect 1.308x1.308 / inner round 1.308 / far side rect 1.308x1.308 hole 0.8: 1(1,2.875)
  round 1.308 hole 0.8: 2(-1,2.875)
  round 1.508 hole 1: SH1(-3.25,2.375) SH2(3.25,2.375) SH3(-3.25,-2.375) SH4(3.25,-2.375)
  silkscreen extent -4.05,-1.58 4.05,4.35, body extent -3.95,-6.02 3.95,3.08, height 4.55
IND_HCB1608KF_TTA [mil]
  rect 34x37 smd paste+0 mask+0: 1(-31.5,0) 2(31.5,0)
  body extent -34,-19 34,19, height 37
IND_SRP1050_BRN [mm]
  rect 2.891x4.751 smd paste+0 mask+0: 1(-4.506,0) 2(4.506,0)
  silkscreen extent -5.32,-5.28 5.32,5.28, body extent -5.65,-5.16 5.65,5.16, height 5.41
J1B1211CCD [mm]
  rect 1.408x1.408 hole 0.9: 1(-4.445,6.35)
  round 1.408 hole 0.9: 2(-3.175,8.89) 3(-1.905,6.35) 4(-0.635,8.89) 5(0.635,6.35) 6(1.905,8.89) 7(3.175,6.35) 8(4.445,8.89)
  round 1.53 hole 1.02: 9(-6.325,-5.08) 10(-3.758,-3.38) 11(3.758,-5.08) 12(6.325,-3.38)
  round 2.4 hole 1.6: 13(-7.75,3.05) 14(7.75,3.05)
  round 3.25 hole 3.25 unplated: ""(-5.715,0) ""(5.715,0)
  silkscreen extent -8,-10.75 8,10.6, body extent -9.61,-10.84 9.61,10.41, height 15.14
JST_BM12B-SRSS-TB(LF)(SN) [mm]
  rect 0.6x1.55 smd: 1(-5.5,-1.775) 2(-4.5,-1.775) 3(-3.5,-1.775) 4(-2.5,-1.775) 5(-1.5,-1.775) 6(-0.5,-1.775) 7(0.5,-1.775) 8(1.5,-1.775) 9(2.5,-1.775) 10(3.5,-1.775) 11(4.5,-1.775) 12(5.5,-1.775)
  rect 1.2x1.8 smd: S1(-6.8,0.75) S2(6.8,0.75)
  silkscreen extent -7,-3.35 7,1.45, body extent -7,-2.14 7,1.46, height 4.25
JST_SM03B-SRSS-TB(LF)(SN) [mm]
  rect 0.6x1.55 smd paste+0 mask+0.102: 1(-1,0) 2(0,0) 3(1,0)
  rect 1.2x1.8 smd paste+0 mask+0.102: S1(-2.3,-3.875) S2(2.3,-3.875)
  silkscreen extent -2.5,-4.57 2.5,0.5, body extent -2.5,-3.9 2.5,1.05, height 3.25
JST_SM06B-SRSS-TB(LF)(SN) [mm]
  rect 0.6x1.55 smd: 1(-2.5,0) 2(-1.5,0) 3(-0.5,0) 4(0.5,0) 5(1.5,0) 6(2.5,0)
  rect 1.2x1.8 smd: S1(-3.8,-3.875) S2(3.8,-3.875)
  silkscreen extent -4,-4.57 4,0.6, body extent -4,-4.57 4,0.38, height 2.95
JST_SM08B-SRSS-TB [mm]
  rect 0.6x1.55 smd: 1(-3.5,4.775) 2(-2.5,4.775) 3(-1.5,4.775) 4(-0.5,4.775) 5(0.5,4.775) 6(1.5,4.775) 7(2.5,4.775) 8(3.5,4.775)
  rect 1.2x1.8 smd: P1(-4.8,0.9) P2(4.8,0.9)
  silkscreen extent -5.08,0.2 3.9,5.71
MHS110FRGBCT [mm]
  rect 0.7x0.8 smd: A(1.4,-0.3) R(-1.4,-0.3)
  rect 0.5x0.55 smd: B(0.4,-0.575) G(-0.4,-0.575)
  silkscreen extent -0.97,0 0.97,1.08
MOLEX_104031-0811 [mm]
  rect 0.85x1.1 smd: 1(3.105,-5.45) 2(2.005,-5.45) 3(0.905,-5.45) 4(-0.195,-5.45) 5(-1.295,-5.45) 6(-2.395,-5.45) 7(-3.495,-5.45)
  rect 0.75x1.1 smd: 8(-4.545,-5.45)
  rect 1.2x1 smd: 9(5.74,0.7) 10(5.74,4.4)
  rect 1.55x1.35 smd: G1(5.565,-5.325)
  rect 1.17x1.8 smd: G2(-5.755,-5.1)
  rect 1.9x1.35 smd: G3(-3.73,5.375) G4(2.24,5.375)
  silkscreen extent -5.97,-6.01 5.97,5.7, body extent -5.98,-5.84 5.98,5.56, height 1.45
QFP50P900X900X160-48N [mm]
  rect 1.56x0.28 smd: 1(-4.18,2.75) 2(-4.18,2.25) 3(-4.18,1.75) 4(-4.18,1.25) 5(-4.18,0.75) 6(-4.18,0.25) 7(-4.18,-0.25) 8(-4.18,-0.75) 9(-4.18,-1.25) 10(-4.18,-1.75) 11(-4.18,-2.25) 12(-4.18,-2.75) 25(4.18,-2.75) 26(4.18,-2.25) 27(4.18,-1.75) 28(4.18,-1.25) 29(4.18,-0.75) 30(4.18,-0.25) 31(4.18,0.25) 32(4.18,0.75) 33(4.18,1.25) 34(4.18,1.75) 35(4.18,2.25) 36(4.18,2.75)
  rect 0.28x1.56 smd: 13(-2.75,-4.18) 14(-2.25,-4.18) 15(-1.75,-4.18) 16(-1.25,-4.18) 17(-0.75,-4.18) 18(-0.25,-4.18) 19(0.25,-4.18) 20(0.75,-4.18) 21(1.25,-4.18) 22(1.75,-4.18) 23(2.25,-4.18) 24(2.75,-4.18) 37(2.75,4.18) 38(2.25,4.18) 39(1.75,4.18) 40(1.25,4.18) 41(0.75,4.18) 42(0.25,4.18) 43(-0.25,4.18) 44(-0.75,4.18) 45(-1.25,4.18) 46(-1.75,4.18) 47(-2.25,4.18) 48(-2.75,4.18)
  silkscreen extent -4.29,-3.55 3.55,3.55
QFP50P2200X2200X160-144N [mm]
  rrect25% 1.56x0.28 smd: 1(-10.68,8.75) 2(-10.68,8.25) 3(-10.68,7.75) 4(-10.68,7.25) 5(-10.68,6.75) 6(-10.68,6.25) 7(-10.68,5.75) 8(-10.68,5.25) 9(-10.68,4.75) 10(-10.68,4.25) 11(-10.68,3.75) 12(-10.68,3.25) 13(-10.68,2.75) 14(-10.68,2.25) 15(-10.68,1.75) 16(-10.68,1.25) 17(-10.68,0.75) 18(-10.68,0.25) 19(-10.68,-0.25) 20(-10.68,-0.75) 21(-10.68,-1.25) 22(-10.68,-1.75) 23(-10.68,-2.25) 24(-10.68,-2.75) 25(-10.68,-3.25) 26(-10.68,-3.75) 27(-10.68,-4.25) 28(-10.68,-4.75) 29(-10.68,-5.25) 30(-10.68,-5.75) 31(-10.68,-6.25) 32(-10.68,-6.75) 33(-10.68,-7.25) 34(-10.68,-7.75) 35(-10.68,-8.25) 36(-10.68,-8.75) 73(10.68,-8.75) 74(10.68,-8.25) 75(10.68,-7.75) 76(10.68,-7.25) 77(10.68,-6.75) 78(10.68,-6.25) 79(10.68,-5.75) 80(10.68,-5.25) 81(10.68,-4.75) 82(10.68,-4.25) 83(10.68,-3.75) 84(10.68,-3.25) 85(10.68,-2.75) 86(10.68,-2.25) 87(10.68,-1.75) 88(10.68,-1.25) 89(10.68,-0.75) 90(10.68,-0.25) 91(10.68,0.25) 92(10.68,0.75) 93(10.68,1.25) 94(10.68,1.75) 95(10.68,2.25) 96(10.68,2.75) 97(10.68,3.25) 98(10.68,3.75) 99(10.68,4.25) 100(10.68,4.75) 101(10.68,5.25) 102(10.68,5.75) 103(10.68,6.25) 104(10.68,6.75) 105(10.68,7.25) 106(10.68,7.75) 107(10.68,8.25) 108(10.68,8.75)
  rrect25% 0.28x1.56 smd: 37(-8.75,-10.68) 38(-8.25,-10.68) 39(-7.75,-10.68) 40(-7.25,-10.68) 41(-6.75,-10.68) 42(-6.25,-10.68) 43(-5.75,-10.68) 44(-5.25,-10.68) 45(-4.75,-10.68) 46(-4.25,-10.68) 47(-3.75,-10.68) 48(-3.25,-10.68) 49(-2.75,-10.68) 50(-2.25,-10.68) 51(-1.75,-10.68) 52(-1.25,-10.68) 53(-0.75,-10.68) 54(-0.25,-10.68) 55(0.25,-10.68) 56(0.75,-10.68) 57(1.25,-10.68) 58(1.75,-10.68) 59(2.25,-10.68) 60(2.75,-10.68) 61(3.25,-10.68) 62(3.75,-10.68) 63(4.25,-10.68) 64(4.75,-10.68) 65(5.25,-10.68) 66(5.75,-10.68) 67(6.25,-10.68) 68(6.75,-10.68) 69(7.25,-10.68) 70(7.75,-10.68) 71(8.25,-10.68) 72(8.75,-10.68) 109(8.75,10.68) 110(8.25,10.68) 111(7.75,10.68) 112(7.25,10.68) 113(6.75,10.68) 114(6.25,10.68) 115(5.75,10.68) 116(5.25,10.68) 117(4.75,10.68) 118(4.25,10.68) 119(3.75,10.68) 120(3.25,10.68) 121(2.75,10.68) 122(2.25,10.68) 123(1.75,10.68) 124(1.25,10.68) 125(0.75,10.68) 126(0.25,10.68) 127(-0.25,10.68) 128(-0.75,10.68) 129(-1.25,10.68) 130(-1.75,10.68) 131(-2.25,10.68) 132(-2.75,10.68) 133(-3.25,10.68) 134(-3.75,10.68) 135(-4.25,10.68) 136(-4.75,10.68) 137(-5.25,10.68) 138(-5.75,10.68) 139(-6.25,10.68) 140(-6.75,10.68) 141(-7.25,10.68) 142(-7.75,10.68) 143(-8.25,10.68) 144(-8.75,10.68)
  silkscreen extent -10.1,-10.1 10.1,10.1, body extent -11,-11 11,11, height 0.72
SO-8EP_DIO [mil]
  rect 56x22 smd paste+0 mask+0: 1(-106,75) 2(-106,25) 3(-106,-25) 4(-106,-75) 5(106,-75) 6(106,-25) 7(106,25) 8(106,75)
  rect 107x132 smd paste-65.5 mask+0: 9(0,0)
  silkscreen extent -99,-103 83,114, body extent -120,-97 120,97, height 64
SOIC127P599X175-8N [mm]
  rrect25% 1.97x0.6 smd paste+0 mask+0.102: 1(-2.47,1.905) 2(-2.47,0.635) 3(-2.47,-0.635) 4(-2.47,-1.905) 5(2.47,-1.905) 6(2.47,-0.635) 7(2.47,0.635) 8(2.47,1.905)
  silkscreen extent -2.62,-2.52 1.95,2.91, body extent -3,-2.45 2.99,2.45, height 1.75
SOIC127P602X173-8N-1-V [mm] "SOIC,1.27mm pitch;8 pin,3.899mm W X 4.889mm L X 1.727mm H body"
  rect 1.47x0.65 smd paste+0 mask+0: 1(-2.77,1.905) 2(-2.77,0.635) 3(-2.77,-0.635) 4(-2.77,-1.905) 5(2.77,-1.905) 6(2.77,-0.635) 7(2.77,0.635) 8(2.77,1.905)
  silkscreen extent -2.85,-2.5 1.7,2.72, body extent -3.01,-2.44 3.01,2.44, height 1.74
SOP50P490X110-10N [mm]
  rrect25% 1.47x0.28 smd paste+0 mask+0.102: 1(-2.15,1) 2(-2.15,0.5) 3(-2.15,0) 4(-2.15,-0.5) 5(-2.15,-1) 6(2.15,-1) 7(2.15,-0.5) 8(2.15,0) 9(2.15,0.5) 10(2.15,1)
  silkscreen extent -2.33,-1.5 1.5,1.86, body extent -2.45,-1.5 2.45,1.5, height 1.1
SOP65P640X120-16N [mm]
  rrect25% 1.57x0.41 smd: 1(-2.87,2.275) 2(-2.87,1.625) 3(-2.87,0.975) 4(-2.87,0.325) 5(-2.87,-0.325) 6(-2.87,-0.975) 7(-2.87,-1.625) 8(-2.87,-2.275) 9(2.87,-2.275) 10(2.87,-1.625) 11(2.87,-0.975) 12(2.87,-0.325) 13(2.87,0.325) 14(2.87,0.975) 15(2.87,1.625) 16(2.87,2.275)
  silkscreen extent -1.77,-2.5 1.77,2.76, body extent -3.2,-2.5 3.2,2.5, height 1.2
SOT95P280X145-6N [mm]
  rrect50% 1.22x0.6 smd: 1(-1.245,0.95) 2(-1.245,0) 3(-1.245,-0.95) 4(1.245,-0.95) 5(1.245,0) 6(1.245,0.95)
  silkscreen extent -1.33,-1.57 0.88,1.71, body extent -1.45,-1.45 1.45,1.45, height 1
SW_KMR221GLFS [mm]
  rect 0.9x1 smd: 1(-2.05,0.8) 2(-2.05,-0.8) 3(2.05,-0.8) 4(2.05,0.8)
  rect 1.7x0.55 smd: 5(0,1.425)
  silkscreen extent -1.2,-1.4 1.2,-1.4, body extent -2.3,-1.4 2.3,1.4, height 0.5
TESTPAD [mm]
  round 1 smd mask+0.05: 1(0,0)
TVS_ESDA7P120-1U1M [mm]
  rect 0.55x0.8 smd: 1(-0.625,0) 2(0.625,0)
  silkscreen extent -1.14,-0.76 0.03,0.76
TVS_LESD5D5.0CT1G [mm]
  rect 0.48x0.4 smd: 1(-0.66,0) 2(0.66,0)
  silkscreen extent -0.6,-0.52 0.6,0.52, body extent -0.8,-0.4 0.8,0.4, height 0.7
XTAL_NX3215SA-32.768KHZ-EXS00A-MU00525 [mm]
  rect 1x1.8 smd paste+0 mask+0.102: 1(-1.25,0) 2(1.25,0)
  body extent -1.6,-0.75 1.6,0.75, height 0.9

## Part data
C1 C2 C3 C4 C7 C12 C13 C14 C15 C16 C17 C18 C19 C20 C21 C22 C23 C24 C25 C27 C28 C29 C30 C31 C32 C33 C34 C35 C36 C37 C38 C39 C40 C41 C42 C43 C44 C45 C46 C47 C51 C52 C53 C54 C55 C56 C57 C58 C59 C60 C61 C62 C63 C64 C65 C67 C68: library part 0603_C
C5 C6: library part 0805_CAP, "0805 cap", Package="2012 AVX"
C8 C9 C10 C11: library part 1206_CAP, "1206 CAP"
C66: "No Description Available", Manufacturer_Name="KYOCERA AVX"
D1 D2 J1 J6 J7: Package=None
D3 D6 D7: "Transient Voltage Suppressors for ESD Protection", Package=None
D4: "- Clamp - Ipp Tvs Diode Surface Mount ST0201", Package="0201 STMicroelectronics"
D5: "RAVE RAVE RAVE / COMMON ANODE"
D8: library part 0603_LED_BLU, Package="0603 WÃ¼rth Elektronik"
D9 D10: library part 0603_LED_GRN, Package="0603 WÃ¼rth Elektronik"
J2: "SH Series 8 Position 1 mm Pitch Surface Mount Side Entry Shrouded Header", Package=None
J3 J4 J5 J8 J9: library part SM04B-SRSS-TBLFSN, "Description", Manufacturer_Name=JST
J10 P9 P10 P11 P12 P13: "Connector Header Surface Mount, Right Angle 3 position 0.039 (1.00mm)", Package=None
L1: "Description", Manufacturer_Name="Bourns Electronics"
L2: "Description", Manufacturer_Name="Tai Tech"
P1: "1 Port RJ45 Magjack Connector Through Hole 10/100 Base-T, AutoMDIX", Package=None
P2 P6: library part SM05B-SRSS-TBLFSN, "Description", Manufacturer_Name=JST
P3 P4 P5 P7 P8: "Connector Header Surface Mount, Right Angle 6 position 0.039 (1.00mm)", Package=None
R1 R2 R3 R4 R5 R6 R7 R8 R9 R10 R11 R12 R13 R14 R15 R16 R17 R18 R19 R20 R21 R22 R23 R24 R25 R26 R27 R28 R29 R30 R31 R32 R33 R34 R35 R36 R37 R38 R39 R40 R41 R42 R43 R44 R45 R46 R47 R48 R49 R50 R51 R52 R53 R54 R55 R56 R57 R58 R59 R60 R61 R62 R63 R64 R65 R66 R67 R68 R69 R70 R71 R72 R73 R74 R75 R76 R77 R78: library part 0603_R
SD1: "Surface Mount Micro SD Card Connector, with Push In Termination", Package=None
SW1 SW2: "Switch Tactile N.O. SPST Button Gull Wing 0.05A 32VDC 1VA 200000Cycles 2N SMD Automotive T/R", Package=None
TP3 TP4: "1.5mm X 1.5mm PAD FOR COMM PROTOCOLS, GPIOS, ADC, TIMERS, ETC"
U1: "17V Clamp 5A (8/20Âµs) Ipp Tvs Diode Surface Mount SOT-23-6", Package="SOT-23-6 STMicroelectronics"
U2: "Description", Manufacturer_Name="Diodes Inc"
U3: "ARMÂ® CortexÂ®-M7 STM32H7 Microcontroller IC 32-Bit Single-Core 480MHz 2MB (2M x 8) FLASH 144-LQFP (20x20)", Package="LQFP-144 STMicroelectronics"
U4 U6: "5-V, 2:1 (SPDT), 4-channel analog switch with powered-off protection & 1.8-V input logic", Package="TSSOP-16 Texas Instruments"
U5 U7 U8: "5-V, 2:1 (SPDT), 2-channel analog switch with powered-off protection", Package="VSSOP-10 Texas Instruments"
U9: "4-Kbit (512 × 8) Serial (SPI) F-RAM", Manufacturer="Infineon Technologies"
U10: "3.3-V CAN Transceivers with CAN FD (Flexible Data Rate)", Package="SOIC-8 Texas Instruments"
U11: "Hardwired TCP/IP embedded Ethernet controller", Package=None
USB1: "USB-C (USB TYPE-C) USB 2.0 Receptacle Connector 24 (16+8 Dummy) Position Through Hole, Right Angle, low cost, 3.46mm profile, 16 pin, horizontal, Top mount", Package=None
X1: "Description", Manufacturer_Name=NDK
Y1: library part NX3215SA-32.768KHZ-EXS00A-MU00525, "32.768 kHz - Crystal 6pF 50 kOhms 2-SMD, No Lead", Package="SMD-2 NDK"
Y2: "Description", Manufacturer_Name=Epson

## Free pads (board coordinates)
  round 6 hole 3.2 mask+0.05: MH1(3.5,3.5) MH1(3.5,61.5) MH1(66,3.556) MH1(66,61.5)

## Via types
v1: diameter 0.451, hole 0.301, L1 to L6, 453 vias
v2: diameter 0.45, hole 0.3, L1 to L6, 5 vias

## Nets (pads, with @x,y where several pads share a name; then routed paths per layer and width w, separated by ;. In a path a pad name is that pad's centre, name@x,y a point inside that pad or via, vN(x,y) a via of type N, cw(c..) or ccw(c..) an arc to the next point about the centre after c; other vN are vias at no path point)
+3.3V: C7.2 C8.2 C9.2 C10.2 C11.2 C13.2 C14.2 C15.2 C16.2 C17.2 C18.2 C19.2 C20.2 C21.2 C22.2 C23.2 C24.2 C25.2 C27.2 C28.2 C34.2 C37.1 C38.1 C39.2 C40.2 C41.2 C42.2 C43.2 C44.2 C45.2 C46.2 C61.2 C62.2 D5.A D10.2 J2.5 J5.1 J6.1 J7.1 J8.1 J9.1 L1.1 L2.2 P1.10 P1.12 P4.1 P7.1 P8.1 R5.2 R9.1 R12.2 R25.1 R26.2 R27.1 R28.1 R29.1 R30.1 R32.2 R33.1 R34.1 R35.1 R36.1 R39.1 R40.1 R41.1 R42.1 R43.1 R44.1 R60.2 R67.2 R70.2 R73.2 R74.2 R75.2 R76.2 SD1.4 SW1.1 SW1.4 TP1.1 U3.6 U3.17 U3.30 U3.32 U3.33 U3.39 U3.52 U3.62 U3.72 U3.84 U3.95 U3.108 U3.121 U3.131 U3.144 U4.16 U5.8 U6.16 U7.8 U8.8 U9.8 U10.3 U11.28 | length 91
  L1 w0.178: v1(20.005,14.998) 20.097,15.09 U9.8@22.099,15.09 ; U3.144@22.279,29.596 23.613,29.596 v1(23.99,29.973) ; U3.131@22.279,36.096 23.455,36.096 v1(23.99,35.561) ; U3.121@22.279,41.096 23.535,41.096 v1(23.99,40.641) ; v1(23.749,47.117) 24.209,47.577 U3.108@24.209,49.026 ; U3.6@26.709,27.666 26.709,28.784 26.798,28.873 v1(26.798,29.477) ; U3.17@32.209,27.666 32.209,29.329 32.511,29.631 v1(32.511,31.229) ; v1(35.923,8.598) 35.923,8.648 36.284,9.009 36.334,9.009 36.342,9.017 39.604,9.017 39.612,9.009 39.662,9.009 40.023,8.648 v1(40.023,8.598) ; U3.84@36.209,49.026 36.209,47.471 37.325,46.355 v1(37.325,45.721) ; v1(38.496,29.579) 38.496,29.506 38.709,29.293 U3.30@38.709,27.666 ; U3.32@39.709,27.666 U3.33@40.209,27.666 ; v1(41.542,42.544) 41.99,42.096 U3.62@43.639,42.096 ; v1(41.923,31.114) 42.441,30.596 U3.39@43.639,30.596 ; v1(43.308,48.019) 43.308,47.986 43.639,47.655 U3.72@43.639,47.096 ; U11.28@49.164,20.692 v1@51.059,20.692 ; v1(51.067,20.7) v1(52.718,20.7) ; v1(85.357,35.178) v1(87.008,35.178) 87.536,35.706 SD1.4@88.624,35.706
  L1 w0.203: v1(9.239,55.059) 9.271,55.091 U8.8@9.271,56.633 ; v1(13.335,55.072) 13.351,55.088 U7.8@13.351,56.624 ; v1(30.366,47.243) 30.366,47.307 30.709,47.65 U3.95@30.709,49.026 ; v1(31.129,8.736) 31.143,8.749 U5.8@32.616,8.749 ; U4.16@37.922,58.028 38.371,58.028 38.474,58.131 v1(38.474,59.804) ; U3.32@39.709,27.666 39.709,25.938 39.964,25.683 39.964,25.326 v1(40.258,25.032) v1(40.258,23.508) ; U3.52@43.639,37.096 45.025,37.096 45.52,37.591 v1(45.58,37.591) ; R43.1@52.458,11.798 v1(52.458,13.322) ; v1(53.531,5.588) 53.531,4.268 v1(54.23,3.569) ; D10.2@86.233,3.051 86.293,3.051 87.433,4.191 v2(87.757,4.191)
  L1 w0.254: v1@52.964,57.012 U6.16@54.305,57.012
  L1 w0.508: v1(55.626,11.176) v1(57.277,11.176) 58.807,11.176 59.03,11.399 L2.2@59.068,11.399
  L3 w0.305: v1(37.325,45.721) v1(38.849,45.721) 38.877,45.749 39.526,45.749 40.176,46.399 40.176,47.161 41.034,48.019 v1(43.308,48.019)
  L6 w0.305: v1(30.366,47.243) 30.644,46.966 31.012,46.966 31.54,46.438 31.54,43.517 33.274,41.783 35.513,41.783 36.274,42.544 37.37,42.544 ; v1(37.325,45.721) 37.325,44.945 36.899,44.519 36.899,43.016 37.37,42.544 ; v1(41.542,42.544) 37.37,42.544
  other v1: 17.767,2.033 19.418,2.033 16.653,5.588 53.975,11.176 2.491,11.777 22.099,13.195 5.588,14.779 37.077,15.761 29.604,16.263 29.604,19.311 5.588,22.59 13.211,22.645 20.307,27.933 32.511,29.705 84.829,30.086 2.668,30.239 84.956,32.118 5.588,33.242 70.833,35.941 62.357,36.454 63.119,36.454 63.881,36.454 64.643,36.454 65.405,36.454 70.833,36.957 62.357,37.216 63.119,37.216 63.881,37.216 64.643,37.216 65.405,37.216 85.464,37.96 62.357,37.978 63.119,37.978 63.881,37.978 64.643,37.978 65.405,37.978 70.833,38.735 82.448,38.742 85.471,39.497 70.833,39.751 82.474,40.111 5.588,41.354 70.833,41.529 70.833,42.545 18.11,42.833 70.833,44.323 70.833,45.339 53.597,47.283 65.17,49.362 67.564,51.562 67.565,53.2 52.946,57.03 21.971,59.309 71.755,60.325 19.317,62.737 21.476,62.737 10.172,63.103 12.05,63.11
+3V3A: C51.2 C52.2 C53.2 C54.2 C55.2 C56.2 C57.2 L2.1 R45.1 R46.1 R47.1 U11.4 U11.8 U11.11 U11.15 U11.17 U11.21 | length 49
  L1 w0.178: v1(51.308,22.098) 51.746,22.098 52.094,22.446 U11.21@52.094,23.622 ; U11.17@54.094,23.622 54.094,21.813 54.23,21.677 v1(54.23,21.603) ; U11.15@55.094,23.622 55.094,24.871 55.288,25.065 55.288,25.683 C55.2@55.5,25.895 ; v1(55.752,19.883) 55.826,19.883 56.135,20.192 U11.8@57.524,20.192 ; v1(55.766,18.668) 56.242,18.192 U11.4@57.524,18.192 ; U11.11@57.524,21.692 58.776,21.692 58.969,21.885 59.235,21.885 v1(59.55,22.2)
  L1 w0.381: R46.1@65.271,11.443 v1(65.271,12.967) R47.1@65.271,14.491
  L6 w0.305: v1(51.308,22.098) 51.308,22.17 52.125,22.987 54.61,22.987 ; v1(55.394,25.789) 55.394,23.156 55.562,22.987
  L6 w0.381: v1(54.23,21.603) 54.23,22.607 54.61,22.987 55.562,22.987 56.515,22.987 57.277,22.225 57.277,20.955 ; C51.2@54.242,18.668 v1(55.766,18.668) 55.752,18.668 v1(55.752,19.883) 55.752,20.081 55.992,20.32 56.642,20.32 57.277,20.955 ; C52.2@55.826,18.668 57.163,17.331 57.163,14.884 v1(59.055,12.992) 65.227,12.992 65.253,12.967 v1(65.271,12.967) ; v1(59.55,22.2) 58.522,22.2 57.277,20.955
+5V: C1.2 C2.2 C3.1 C5.2 C6.2 D1.1 D2.1 D9.2 J1.1 J4.1 J6.2 J7.2 P5.6 R1.2 U1.5 U2.2 U2.3 USB1.A4 USB1.A9 USB1.B4 USB1.B9 | length 267.1
  L1 w0.254: U1.5@75.717,58.547 76.708,58.547 76.962,58.801 76.962,60.421 ; v1(76.949,61.207) 76.949,60.421 79.279,60.421 79.725,59.975 80.243,59.975 D1.1@80.391,59.827
  L1 w0.381: U2.3@76.479,49.911 U2.2@76.479,48.641 77.522,48.641 77.688,48.806 v1(78.486,48.806)
  L1 w0.508: D1.1@80.391,59.827 80.412,59.848 81.057,59.848 81.361,60.152 USB1.A9@82.216,60.152 USB1.B4@83.566,60.152 ; R1.2@80.517,55.893 USB1.A4@82.207,55.893 ; USB1.A4@82.216,55.902 USB1.B9@83.566,55.902 ; v2(82.804,4.191) 83.566,4.191 83.965,3.792 83.965,3.227 84.141,3.051 D9.2@84.201,3.051
  L4 w0.381: J1.1@81.834,49.133 81.852,49.151 83.06,49.151 83.693,49.784 87.884,49.784 88.742,50.642 88.742,57.181 85.771,60.152 USB1.B4@83.566,60.152
  L4 w0.508: v1(9.318,59.548) 9.318,58.627 10.414,57.531 24.892,57.531 31.369,51.054 45.212,51.054 49.983,46.283 v1(53.597,46.283) 56.951,46.283 58.801,48.133 ; v1(13.211,21.645) 14.423,21.645 15.367,20.701 15.367,13.716 19.304,9.779 25.654,9.779 27.94,12.065 35.433,12.065 ; v1(32.417,5.588) 32.417,9.049 35.433,12.065 ; v1(76.949,61.207) 75.05,61.207 73.406,59.563 73.406,57.023 71.628,55.245 61.087,55.245 58.801,52.959 58.801,48.133 ; v2(82.804,4.191) 81.664,3.051 76.324,3.051 70.612,8.763 61.849,8.763 60.452,10.16 50.038,10.16 47.371,12.827 47.371,16.51 ; 35.433,12.065 42.926,12.065 47.371,16.51 ; 47.371,16.51 47.371,19.431 46.482,20.32 46.482,21.463 48.641,23.622 48.641,29.21 52.324,32.893 56.642,32.893 58.801,35.052 58.801,48.133
  L6 w0.381: J1.1@81.834,49.133 82.661,49.133 ; 83.133,49.133 82.661,49.133 ; D2.1@84.084,50.165 84.084,48.637 v1(83.96,48.513) ; v1(85.611,48.513) v1(83.96,48.513) ; 82.661,49.133 83.28,49.133 83.9,48.513 v1(83.96,48.513)
  other v1: 79.502,48.806
ACTLED: R54.2 U11.27 | length 28.5
  L1 w0.203: v1(47.498,21.082) 47.565,21.082 47.675,21.192 U11.27@49.164,21.192
  L6 w0.178: v1(47.498,21.082) 47.505,21.075 47.505,13.582 50.927,10.16 65.018,10.16 v1(65.272,9.906)
BOOT0: J2.7 R13.1 SW1.2 SW1.3 U3.138 | length 78.8
  L1 w0.178: U3.138@22.279,32.596 24.427,32.596 25.527,31.496 v1(25.527,29.337) ; v1(35.923,10.198) v1(40.023,10.198)
  L6 w0.178: R13.1@3.69,40.145 3.69,40.085 4.031,39.744 4.085,39.744 4.475,39.354 v1(5.588,39.354) 10.049,39.354 10.795,38.608 19.05,38.608 25.146,32.512 25.146,31.115 25.527,30.734 v1(25.527,29.337) 18.669,22.479 18.669,12.7 23.749,7.62 27.813,7.62 28.956,6.477 30.226,6.477 30.607,6.858 32.583,6.858 v1(35.923,10.198)
CAN_RX: U3.114 U10.4 | length 4.5
  L1 w0.178: U10.4@18.11,43.849 19.719,43.849 20.466,44.596 U3.114@22.279,44.596
CAN_TX: U3.115 U10.1 | length 7.5
  L1 w0.178: U10.1@18.11,40.039 19.546,40.039 20.32,40.813 20.32,43.561 20.855,44.096 U3.115@22.279,44.096
CANH: J5.2 R37.1 U10.7 | length 25.6
  L1 w0.178: J5.2@5.588,21.59 4.445,21.59 4.064,21.971 4.064,24.257 11.176,31.369 11.176,40.686 11.798,41.309 U10.7@13.17,41.309
  other v1: 13.595,41.294
CANL: J5.3 R38.2 U10.6 | length 28.7
  L1 w0.178: J5.3@5.588,20.59 4.175,20.59 3.429,21.336 3.429,24.257 10.541,31.369 10.541,41.656 11.464,42.579 U10.6@13.17,42.579
  other v1: 13.609,42.573
CGND: C66.2 P1.8 P1.13 P1.14
D_N: U1.1 USB1.A7 USB1.B7 | length 6.1
  L6 w0.178: v1(78.207,57.597) 78.933,57.597 79.707,58.371 82.135,58.371 USB1.A7@82.216,58.452 82.306,58.362 82.57,58.362 82.651,58.281 82.897,58.281 USB1.B7@83.566,57.612
D_P: U1.3 USB1.A6 USB1.B6 | length 6.5
  L1 w0.178: U1.3@78.207,59.497 79.187,59.497 81.082,57.602 USB1.A6@82.216,57.602 82.306,57.692 82.581,57.692 83.25,58.362 83.476,58.362 USB1.B6@83.566,58.452
DOUT_N: U1.6 U3.103 | length 54.4
  L1 w0.178: U3.103@26.709,49.026 26.709,50.15 27.105,50.546 v1(27.178,50.546)
  L6 w0.178: v1@27.189,50.557 27.796,51.164 57.26,51.164 62.865,56.769 68.58,56.769 70.866,59.055 74.259,59.055 v1(75.717,57.597)
DOUT_P: U1.4 U3.104 | length 54.9
  L1 w0.178: U3.104@26.209,49.026 26.209,50.847 v1(26.543,51.181)
  L6 w0.178: v1(26.543,51.181) 26.975,51.613 57.074,51.613 62.662,57.201 68.401,57.201 70.697,59.497 v1(75.717,59.497)
DSHOT1_OUT: R63.1 U4.4 | length 10.7
  L1 w0.178: U4.4@32.182,56.078 33.345,56.078 33.782,56.515 v1(33.782,57.277)
  L6 w0.178: v1(33.782,57.277) 34.29,57.785 36.957,57.785 37.726,57.016 v1(41.389,57.016)
DSHOT2_OUT: R64.2 U4.7 | length 13.2
  L1 w0.178: U4.7@32.182,54.128 33.861,54.128 34.089,54.356 v1(34.163,54.356)
  L6 w0.178: v1(34.163,54.356) 34.925,55.118 34.925,56.515 35.306,56.896 36.957,56.896 37.465,56.388 42.303,56.388 v1(42.939,57.024)
DSHOT3_OUT: R65.1 U4.9 | length 9
  L1 w0.178: U4.9@37.922,53.478 38.013,53.387 39.798,53.387 40.132,53.721 40.132,54.489 40.513,54.87 42.297,54.87 43.307,55.88 44.068,55.88 44.437,56.249 R65.1@44.437,57.016
DSHOT4_OUT: R66.2 U4.12 | length 8.7
  L1 w0.178: U4.12@37.922,55.428 39.352,55.428 39.55,55.626 v1(39.624,55.626)
  L6 w0.178: v1(39.624,55.626) 44.589,55.626 v1(45.987,57.024)
ESC_DISCONNECT: R19.2 U3.69 | length 13
  L1 w0.178: R19.2@41.161,54.103 41.221,54.103 41.562,53.762 41.562,53.702 46.482,48.782 46.482,46.609 45.469,45.596 U3.69@43.639,45.596
ESC_GPIO: J10.2 R12.1 U3.78 | length 24.1
  L1 w0.178: J10.2@27.686,59.436 27.686,60.452 28.067,60.833 29.21,60.833 29.591,60.452 29.591,53.721 31.75,51.562 37.846,51.562 39.209,50.199 U3.78@39.209,49.026 39.209,47.611 v1(38.849,47.251)
ESC_SEL: R21.2 U3.70 U4.1 | length 27.2
  L1 w0.178: U4.1@32.182,58.028 32.268,58.028 32.384,58.144 v1(32.384,59.55) ; v1(41.529,52.451) 42.202,52.451 46.101,48.552 46.101,47.117 45.08,46.096 U3.70@43.639,46.096
  L6 w0.178: v1(32.384,59.55) 32.384,54.992 35.306,52.07 41.089,52.07 41.47,52.451 v1(41.529,52.451)
ETH_INTn: R43.2 U3.56 U11.36 | length 34.1
  L1 w0.178: U3.56@43.639,39.096 46.248,39.096 47.117,38.227 v1(47.117,35.433) ; U11.36@49.164,16.692 48.565,16.692 48.514,16.641 48.514,15.547 49.657,14.404 49.657,12.573 50.335,11.895 50.842,11.895 R43.2@50.928,11.809
  L6 w0.178: v1(47.117,35.433) 47.117,26.797 48.387,25.527 48.387,20.701 48.006,20.32 48.006,16.129 v1(48.514,15.621)
ETH_MISO: U3.20 U11.34 | length 32.6
  L1 w0.178: U3.20@33.709,27.666 33.709,26.459 32.385,25.135 32.385,17.062 33.191,16.256 v1(34.671,16.256) ; v1(38.839,13.505) 39.708,13.505 40.121,13.092 45.35,13.092 47.117,14.859 47.117,16.764 48.045,17.692 U11.34@49.164,17.692
  L6 w0.178: v1(34.671,16.256) 35.56,16.256 38.311,13.505 v1(38.839,13.505)
ETH_MOSI: U3.21 U11.35 | length 35.2
  L1 w0.178: v1(33.782,13.97) 35.084,12.668 45.688,12.668 47.625,14.605 47.625,16.637 48.18,17.192 U11.35@49.164,17.192 ; v1(34.163,25.781) 34.186,25.804 34.186,27.643 U3.21@34.209,27.666
  L6 w0.178: v1(33.782,13.97) 33.715,13.97 31.75,15.935 31.75,24.384 32.821,25.455 33.837,25.455 v1(34.163,25.781)
ETH_RSTn: R39.2 U3.57 U11.37 | length 32.2
  L1 w0.178: U3.57@43.639,39.596 46.51,39.596 48.006,38.1 v1(48.006,36.449) ; v1(49.784,15.494) 50.291,14.987 50.543,14.987 U11.37@50.594,15.037 ; U11.37@50.594,15.262 U11.37@50.594,15.037 ; v1(50.928,13.322) 50.594,13.656 U11.37@50.594,15.037
  L6 w0.178: v1(48.006,36.449) 48.006,34.29 47.498,33.782 47.498,27.178 48.895,25.781 48.895,20.32 48.514,19.939 48.514,16.764 v1(49.784,15.494)
ETH_SCLK: U3.19 U11.33 | length 32.8
  L1 w0.178: U3.19@33.209,27.666 33.209,26.56 31.942,25.292 31.942,16.866 33.06,15.748 34.057,15.748 35.508,14.297 39.634,14.297 40.414,13.517 44.886,13.517 46.609,15.24 46.609,16.847 47.954,18.192 U11.33@49.164,18.192
ETH_SCSN: R44.2 U3.18 U11.32 | length 34.1
  L1 w0.178: U3.18@32.709,27.666 32.709,26.6 31.547,25.439 31.547,16.613 33.175,14.986 v1(33.782,14.986) ; v1(35.814,14.986) 36.519,14.986 36.526,14.979 37.128,14.979 37.375,14.732 38.608,14.732 39.878,14.732 40.692,13.918 44.398,13.918 46.101,15.621 46.101,17.031 47.762,18.692 U11.32@49.164,18.692 ; 38.607,14.733 R44.2@38.607,15.761
  L6 w0.178: v1(33.782,14.986) v1(35.814,14.986)
EXRES1: R58.2 U11.10 | length 3.7
  L1 w0.178: U11.10@57.524,21.192 60.641,21.192 61.04,21.591 R58.2@61.1,21.591
FMU_DSHOT1_IN: P2.1 U4.2 | length 7
  L1 w0.178: U4.2@32.182,57.378 30.887,57.378 30.574,57.691 30.574,59.61 31.676,60.712 P2.1@33.433,60.712
FMU_DSHOT2_IN: P2.2 U4.5 | length 7.1
  L1 w0.178: U4.5@32.182,55.428 33.457,55.428 34.64,56.611 34.64,60.505 P2.2@34.433,60.712
FMU_DSHOT3_IN: P2.3 U4.11 | length 8
  L1 w0.178: P2.3@35.433,60.712 35.33,60.609 35.33,55.729 36.281,54.778 U4.11@37.922,54.778
FMU_DSHOT4_IN: P2.4 U4.14 | length 5.4
  L1 w0.178: P2.4@36.433,60.712 36.269,60.547 36.269,57.33 36.871,56.728 U4.14@37.922,56.728
FMU_UART1_RX: P10.3 U3.137 | length 36.5
  L1 w0.178: P10.3@11.809,5.526 11.809,6.729 9.652,8.886 9.652,25.273 17.475,33.096 U3.137@22.279,33.096
FMU_UART1_TX: P10.2 U3.136 | length 37.2
  L1 w0.178: P10.2@10.809,5.526 10.809,6.742 9.144,8.407 9.144,25.527 17.213,33.596 U3.136@22.279,33.596
FRAM_CS: R28.2 U3.3 U9.1 | length 18.9
  L1 w0.178: U3.3@25.209,27.666 25.209,26.521 24.85,26.162 23.622,26.162 23.241,25.781 23.241,22.555 23.444,22.352 24.13,22.352 24.511,21.971 24.511,21.333 25.796,20.049 25.796,16.101 26.622,15.275 27.5,15.275 U9.1@27.662,15.113 29.164,15.113 29.544,14.733 R28.2@29.604,14.733
FRAM_MISO: R31.1 U3.4 | length 3.4
  L1 w0.178: R31.1@24.27,24.899 24.33,24.899 25.707,26.276 25.709,26.276 U3.4@25.709,27.666
FRAM_MOSI: R11.1 U9.5 | length 2.2
  L1 w0.178: R11.1@21.71,20.841 21.71,19.159 21.946,18.923 U9.5@22.122,18.923
FRAM_SCK: R10.1 U9.6 | length 2.3
  L1 w0.178: R10.1@20.053,18.154 20.356,17.851 21.924,17.851 U9.6@22.122,17.653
